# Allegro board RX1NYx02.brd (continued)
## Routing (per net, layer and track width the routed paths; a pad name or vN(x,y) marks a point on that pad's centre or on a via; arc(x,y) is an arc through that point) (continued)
GND_BD2: length 1820
  TOP w0.102: v1(184.07,-56.57) 184.08,-56.58 U27.3
  TOP w0.254: C77.1 195.92,-36.63 v1(195.69,-36.4) ; C78.1 195.92,-39.8 v1(195.69,-39.57) ; C85.2 v1(186.39,-62.01) ; C79.1 195.92,-28.63 v1(195.69,-28.4) ; C83.1 195.92,-33.45 v1(195.69,-33.22) ; U25.9 v1(187.09,-67.25) ; C76.1 v1(187.42,-31.32) ; C75.2 v1(169.39,-48.46) ; C167.2 v1(186.69,-58.17) ; v1(187.45,-37.67) 187.46,-37.67 C82.1
  TOP w0.381: P_OCP2.A38 v1(274.7,-33.22) ; P_OCP2.A28 v1(274.7,-42.63) ; U17.3 187.17,-33.75 186.78,-34.13 v1(186.78,-34.87) ; P_OCP2.A25 v1(274.7,-44.43) ; v1(274.7,-15.11) v1(276.14,-15.11) ; v1(276.14,-49.83) 276.11,-49.86 v1(274.7,-49.86) ; v1(276.14,-16.91) v1(274.7,-16.91) ; U23.3 v1(190.98,-35.14) ; U22.3 187.49,-40.72 187.87,-41.1 v1(188.44,-41.1) ; v1(276.14,-25.91) v1(274.7,-25.91) ; v1(276.14,-51.63) v1(274.7,-51.63) ; v1(276.14,-24.11) v1(274.7,-24.11) ; v1(276.14,-18.71) v1(274.7,-18.71) ; U18.3 v1(190.98,-41.49) ; P_OCP2.A29 v1(274.7,-38.62) ; v1(276.14,-11.51) v1(274.7,-11.51) ; U19.3 v1(190.98,-38.32) ; v1(274.7,-63.82) v1(276.14,-63.82) ; P_OCP2.A32 v1(274.7,-36.82) ; v1(276.14,-65.62) v1(274.7,-65.62) ; v1(276.14,-22.31) v1(274.7,-22.31) ; P_OCP2.A35 v1(274.7,-35.02) ; v1(276.14,-20.51) v1(274.7,-20.51) ; P_OCP2.A19 v1(274.7,-48.03) ; U20.1 v1(179.16,-48.46) ; U21.3 v1(190.98,-30.32) ; v1(276.14,-13.31) v1(274.7,-13.31) ; P_OCP2.A41 v1(274.7,-31.42) ; P_OCP2.A22 v1(274.7,-46.23)
  TOP w0.508: C165.1 179.75,-51.08 v1(179.04,-50.37) ; DS_BD2_PWR.2 v1(172.43,-65.48) ; C156.1 v1(181.5,-63.58) ; SW3.2 v1(186.53,-36.27) ; C158.1 v1(181.5,-68.15) ; Q3.2 v1(171.48,-50.18)
  GND w0.254: 249.52,-73.16 P_BD2_CLK2_P.2 ; P_BD2_CLK2_P.2 250.65,-73.16 ; P_BD2_CLK2_P.2 249.52,-74.29 ; P_BD2_CLK2_P.2 250.65,-74.29 ; 177.59,-17.81 P_OCP_CPU_13_P.4 ; P_OCP_CPU_13_P.4 178.72,-17.81 ; P_OCP_CPU_13_P.4 178.72,-18.94 ; P_OCP_CPU_13_P.4 177.59,-18.94 ; 234.74,-34.67 P_CPU_OCP_13_N.4 ; P_CPU_OCP_13_N.4 235.87,-34.67 ; P_CPU_OCP_13_N.4 234.74,-33.54 ; P_CPU_OCP_13_N.4 235.87,-33.54 ; P_OCP_CPU_10_P.3 201.58,-18.94 ; P_OCP_CPU_10_P.3 200.45,-18.94 ; P_OCP_CPU_10_P.3 200.45,-17.81 ; P_OCP_CPU_10_P.3 201.58,-17.81 ; P_CPU_OCP_8_N.2 263.03,-53.81 ; P_CPU_OCP_8_N.2 261.9,-54.94 ; P_CPU_OCP_8_N.2 263.03,-54.94 ; P_CPU_OCP_8_N.2 261.9,-53.81 ; P_CPU_OCP_12_P.2 247.3,-23.05 ; P_CPU_OCP_12_P.2 246.17,-23.05 ; P_CPU_OCP_12_P.2 246.17,-21.92 ; P_CPU_OCP_12_P.2 247.3,-21.92 ; 193.32,-61.91 P_BD2_CMTS_N.5 ; P_BD2_CMTS_N.5 194.45,-61.91 ; P_BD2_CMTS_N.5 194.45,-60.78 ; P_BD2_CMTS_N.5 193.32,-60.78 ; 200.45,-22.29 P_OCP_CPU_10_P.2 ; P_OCP_CPU_10_P.2 201.58,-22.29 ; P_OCP_CPU_10_P.2 200.45,-21.16 ; P_OCP_CPU_10_P.2 201.58,-21.16 ; P_CPU_OCP_15_P.2 250.65,-12.57 ; P_CPU_OCP_15_P.2 249.52,-12.57 ; P_CPU_OCP_15_P.2 249.52,-11.44 ; P_CPU_OCP_15_P.2 250.65,-11.44 ; P_CPU_OCP_10_N.2 240.17,-54.18 ; P_CPU_OCP_10_N.2 239.04,-53.05 ; P_CPU_OCP_10_N.2 239.04,-54.18 ; P_CPU_OCP_10_N.2 240.17,-53.05 ; 235.69,-11.81 P_CPU_OCP_14_P.5 ; P_CPU_OCP_14_P.5 235.69,-10.68 ; P_CPU_OCP_14_P.5 236.82,-10.68 ; P_CPU_OCP_14_P.5 236.82,-11.81 ; P_BD2_TRIG_IN_N.2 181.75,-69.81 ; P_BD2_TRIG_IN_N.2 180.62,-69.81 ; P_BD2_TRIG_IN_N.2 180.62,-70.94 ; P_BD2_TRIG_IN_N.2 181.75,-70.94 ; 239.04,-56.4 P_CPU_OCP_10_N.3 ; P_CPU_OCP_10_N.3 240.17,-56.4 ; P_CPU_OCP_10_N.3 239.04,-57.53 ; P_CPU_OCP_10_N.3 240.17,-57.53 ; 189.02,-69.81 P_BD2_CMTS_P.5 ; P_BD2_CMTS_P.5 189.02,-70.94 ; P_BD2_CMTS_P.5 190.15,-70.94 ; P_BD2_CMTS_P.5 190.15,-69.81 ; P_OCP_CPU_13_N.5 191.1,-23.24 ; P_OCP_CPU_13_N.5 191.1,-22.11 ; P_OCP_CPU_13_N.5 189.97,-23.24 ; P_OCP_CPU_13_N.5 189.97,-22.11 ; 234.74,-18.94 P_CPU_OCP_13_P.3 ; P_CPU_OCP_13_P.3 235.87,-18.94 ; P_CPU_OCP_13_P.3 234.74,-17.81 ; P_CPU_OCP_13_P.3 235.87,-17.81 ; P_OCP_CPU_9_N.2 217.31,-53.05 ; P_OCP_CPU_9_N.2 217.31,-54.18 ; P_OCP_CPU_9_N.2 216.18,-53.05 ; P_OCP_CPU_9_N.2 216.18,-54.18 ; P_BD2_CMTS_P.2 194.45,-69.81 ; P_BD2_CMTS_P.2 194.45,-70.94 ; P_BD2_CMTS_P.2 193.32,-70.94 ; P_BD2_CMTS_P.2 193.32,-69.81 ; P_BD2_CLK2_N.2 259.68,-68.86 ; P_BD2_CLK2_N.2 258.55,-69.99 ; P_BD2_CLK2_N.2 259.68,-69.99 ; P_BD2_CLK2_N.2 258.55,-68.86 ; P_OCP_CPU_13_P.5 182.07,-17.81 ; P_OCP_CPU_13_P.5 180.94,-17.81 ; P_OCP_CPU_13_P.5 180.94,-18.94 ; P_OCP_CPU_13_P.5 182.07,-18.94 ; P_CPU_OCP_10_P.5 240.17,-45.15 ; P_CPU_OCP_10_P.5 239.04,-44.02 ; P_CPU_OCP_10_P.5 240.17,-44.02 ; P_CPU_OCP_10_P.5 239.04,-45.15 ; 211.88,-45.15 P_OCP_CPU_9_P.2 ; P_OCP_CPU_9_P.2 211.88,-44.02 ; P_OCP_CPU_9_P.2 213.01,-45.15 ; P_OCP_CPU_9_P.2 213.01,-44.02 ; P_OCP_CPU_12_P.3 224.44,-18.94 ; P_OCP_CPU_12_P.3 224.44,-17.81 ; P_OCP_CPU_12_P.3 223.31,-18.94 ; P_OCP_CPU_12_P.3 223.31,-17.81 ; 188.59,-45.39 P8.2 ; P8.2 190.06,-45.39 ; P8.2 188.59,-43.92 ; P8.2 190.06,-43.92 ; P_BD2_CLK1_P.4 201.58,-68.86 ; P_BD2_CLK1_P.4 200.45,-69.99 ; P_BD2_CLK1_P.4 200.45,-68.86 ; P_BD2_CLK1_P.4 201.58,-69.99 ; 227.61,-54.18 P_OCP_CPU_8_N.2 ; P_OCP_CPU_8_N.2 228.74,-54.18 ; P_OCP_CPU_8_N.2 227.61,-53.05 ; P_OCP_CPU_8_N.2 228.74,-53.05 ; P_CPU_OCP_9_N.2 251.6,-54.94 ; P_CPU_OCP_9_N.2 250.47,-53.81 ; P_CPU_OCP_9_N.2 250.47,-54.94 ; P_CPU_OCP_9_N.2 251.6,-53.81 ; P_BD2_CLK0_P.5 227.79,-69.99 ; P_BD2_CLK0_P.5 226.66,-69.99 ; P_BD2_CLK0_P.5 226.66,-68.86 ; P_BD2_CLK0_P.5 227.79,-68.86 ; 223.31,-57.53 P_OCP_CPU_8_N.4 ; P_OCP_CPU_8_N.4 224.44,-57.53 ; P_OCP_CPU_8_N.4 224.44,-56.4 ; P_OCP_CPU_8_N.4 223.31,-56.4 ; 250.47,-18.57 P_CPU_OCP_12_P.4 ; P_CPU_OCP_12_P.4 251.6,-18.57 ; P_CPU_OCP_12_P.4 251.6,-19.7 ; P_CPU_OCP_12_P.4 250.47,-19.7 ; 239.04,-73.16 P_BD2_CLK0_N.4 ; P_BD2_CLK0_N.4 240.17,-74.29 ; P_BD2_CLK0_N.4 239.04,-74.29 ; P_BD2_CLK0_N.4 240.17,-73.16 ; P_BD2_CMTS_P.4 190.15,-73.16 ; P_BD2_CMTS_P.4 189.02,-74.29 ; P_BD2_CMTS_P.4 189.02,-73.16 ; P_BD2_CMTS_P.4 190.15,-74.29 ; P_CPU_OCP_15_N.5 259.68,-12.57 ; P_CPU_OCP_15_N.5 259.68,-11.44 ; P_CPU_OCP_15_N.5 258.55,-11.44 ; P_CPU_OCP_15_N.5 258.55,-12.57 ; 261.9,-57.16 P_CPU_OCP_8_N.3 ; P_CPU_OCP_8_N.3 263.03,-58.29 ; P_CPU_OCP_8_N.3 261.9,-58.29 ; P_CPU_OCP_8_N.3 263.03,-57.16 ; BD2_P_OCP_CPU_0_P.3 201.58,-41.8 ; BD2_P_OCP_CPU_0_P.3 201.58,-40.67 ; BD2_P_OCP_CPU_0_P.3 200.45,-41.8 ; BD2_P_OCP_CPU_0_P.3 200.45,-40.67 ; P_OCP_CPU_11_N.2 217.31,-30.19 ; P_OCP_CPU_11_N.2 216.18,-30.19 ; P_OCP_CPU_11_N.2 217.31,-31.32 ; P_OCP_CPU_11_N.2 216.18,-31.32 ; P_OCP_CPU_12_P.5 228.74,-22.29 ; P_OCP_CPU_12_P.5 227.61,-21.16 ; P_OCP_CPU_12_P.5 227.61,-22.29 ; P_OCP_CPU_12_P.5 228.74,-21.16 ; P_BD2_TRIG_IN_N.3 181.75,-73.16 ; P_BD2_TRIG_IN_N.3 181.75,-74.29 ; P_BD2_TRIG_IN_N.3 180.62,-74.29 ; P_BD2_TRIG_IN_N.3 180.62,-73.16 ; P_OCP_CPU_8_P.5 228.74,-44.02 ; P_OCP_CPU_8_P.5 227.61,-45.15 ; P_OCP_CPU_8_P.5 227.61,-44.02 ; P_OCP_CPU_8_P.5 228.74,-45.15 ; P_OCP_CPU_9_N.3 217.31,-56.4 ; P_OCP_CPU_9_N.3 216.18,-57.53 ; P_OCP_CPU_9_N.3 216.18,-56.4 ; P_OCP_CPU_9_N.3 217.31,-57.53 ; 193.32,-6.38 P_OCP_CPU_14_P.3 ; P_OCP_CPU_14_P.3 194.45,-7.51 ; P_OCP_CPU_14_P.3 193.32,-7.51 ; P_OCP_CPU_14_P.3 194.45,-6.38 ; P_CPU_OCP_12_N.2 251.6,-32.08 ; P_CPU_OCP_12_N.2 250.47,-30.95 ; P_CPU_OCP_12_N.2 251.6,-30.95 ; P_CPU_OCP_12_N.2 250.47,-32.08 ; 250.47,-41.43 P_CPU_OCP_9_P.4 ; P_CPU_OCP_9_P.4 250.47,-42.56 ; P_CPU_OCP_9_P.4 251.6,-42.56 ; P_CPU_OCP_9_P.4 251.6,-41.43 ; P_CPU_OCP_11_N.2 263.03,-30.95 ; P_CPU_OCP_11_N.2 261.9,-32.08 ; P_CPU_OCP_11_N.2 261.9,-30.95 ; P_CPU_OCP_11_N.2 263.03,-32.08 ; 257.6,-35.43 P_CPU_OCP_11_N.4 ; P_CPU_OCP_11_N.4 258.73,-35.43 ; P_CPU_OCP_11_N.4 258.73,-34.3 ; P_CPU_OCP_11_N.4 257.6,-34.3 ; 211.88,-34.67 P_OCP_CPU_11_N.4 ; P_OCP_CPU_11_N.4 211.88,-33.54 ; P_OCP_CPU_11_N.4 213.01,-33.54 ; P_OCP_CPU_11_N.4 213.01,-34.67 ; 223.31,-30.19 P_OCP_CPU_12_N.5 ; P_OCP_CPU_12_N.5 223.31,-31.32 ; P_OCP_CPU_12_N.5 224.44,-31.32 ; P_OCP_CPU_12_N.5 224.44,-30.19 ; P_OCP_CPU_8_P.2 224.44,-44.02 ; P_OCP_CPU_8_P.2 223.31,-44.02 ; P_OCP_CPU_8_P.2 223.31,-45.15 ; P_OCP_CPU_8_P.2 224.44,-45.15 ; 200.45,-56.4 BD2_P_OCP_CPU_0_N.4 ; BD2_P_OCP_CPU_0_N.4 200.45,-57.53 ; BD2_P_OCP_CPU_0_N.4 201.58,-57.53 ; BD2_P_OCP_CPU_0_N.4 201.58,-56.4 ; 223.31,-6.38 P_CPU_OCP_14_N.4 ; P_CPU_OCP_14_N.4 223.31,-7.51 ; P_CPU_OCP_14_N.4 224.44,-6.38 ; P_CPU_OCP_14_N.4 224.44,-7.51 ; P_BD2_TRIG_IN_P.3 177.45,-58.56 ; P_BD2_TRIG_IN_P.3 176.32,-58.56 ; P_BD2_TRIG_IN_P.3 177.45,-57.43 ; P_BD2_TRIG_IN_P.3 176.32,-57.43 ; P_CPU_OCP_10_P.2 235.87,-44.02 ; P_CPU_OCP_10_P.2 234.74,-45.15 ; P_CPU_OCP_10_P.2 234.74,-44.02 ; P_CPU_OCP_10_P.2 235.87,-45.15 ; P_CPU_OCP_15_P.3 247.3,-11.44 ; P_CPU_OCP_15_P.3 246.17,-12.57 ; P_CPU_OCP_15_P.3 246.17,-11.44 ; P_CPU_OCP_15_P.3 247.3,-12.57 ; P_CPU_OCP_13_N.2 240.17,-31.32 ; P_CPU_OCP_13_N.2 240.17,-30.19 ; P_CPU_OCP_13_N.2 239.04,-30.19 ; P_CPU_OCP_13_N.2 239.04,-31.32 ; 246.17,-8.27 P_CPU_OCP_15_P.4 ; P_CPU_OCP_15_P.4 246.17,-7.14 ; P_CPU_OCP_15_P.4 247.3,-8.27 ; P_CPU_OCP_15_P.4 247.3,-7.14 ; P_CPU_OCP_8_P.2 258.73,-45.91 ; P_CPU_OCP_8_P.2 257.6,-44.78 ; P_CPU_OCP_8_P.2 257.6,-45.91 ; P_CPU_OCP_8_P.2 258.73,-44.78 ; P_OCP_CPU_8_N.3 228.74,-57.53 ; P_OCP_CPU_8_N.3 228.74,-56.4 ; P_OCP_CPU_8_N.3 227.61,-57.53 ; P_OCP_CPU_8_N.3 227.61,-56.4 ; P_OCP_CPU_10_P.5 205.88,-21.16 ; P_OCP_CPU_10_P.5 204.75,-22.29 ; P_OCP_CPU_10_P.5 204.75,-21.16 ; P_OCP_CPU_10_P.5 205.88,-22.29 ; 257.6,-41.43 P_CPU_OCP_8_P.3 ; P_CPU_OCP_8_P.3 258.73,-42.56 ; P_CPU_OCP_8_P.3 257.6,-42.56 ; P_CPU_OCP_8_P.3 258.73,-41.43 ; 204.75,-40.67 BD2_P_OCP_CPU_0_P.4 ; BD2_P_OCP_CPU_0_P.4 204.75,-41.8 ; BD2_P_OCP_CPU_0_P.4 205.88,-40.67 ; BD2_P_OCP_CPU_0_P.4 205.88,-41.8 ; P_BD2_CLK1_P.5 204.93,-69.99 ; P_BD2_CLK1_P.5 204.93,-68.86 ; P_BD2_CLK1_P.5 203.8,-68.86 ; P_BD2_CLK1_P.5 203.8,-69.99 ; P_BD2_CLK0_P.4 224.44,-69.99 ; P_BD2_CLK0_P.4 223.31,-68.86 ; P_BD2_CLK0_P.4 224.44,-68.86 ; P_BD2_CLK0_P.4 223.31,-69.99 ; 180.94,-6.38 P_OCP_CPU_14_N.5 ; P_OCP_CPU_14_N.5 180.94,-7.51 ; P_OCP_CPU_14_N.5 182.07,-6.38 ; P_OCP_CPU_14_N.5 182.07,-7.51 ; 227.61,-40.67 P_OCP_CPU_8_P.4 ; P_OCP_CPU_8_P.4 228.74,-40.67 ; P_OCP_CPU_8_P.4 227.61,-41.8 ; P_OCP_CPU_8_P.4 228.74,-41.8 ; 216.18,-45.15 P_OCP_CPU_9_P.5 ; P_OCP_CPU_9_P.5 217.31,-44.02 ; P_OCP_CPU_9_P.5 217.31,-45.15 ; P_OCP_CPU_9_P.5 216.18,-44.02 ; P_CPU_OCP_8_P.4 263.03,-41.43 ; P_CPU_OCP_8_P.4 263.03,-42.56 ; P_CPU_OCP_8_P.4 261.9,-42.56 ; P_CPU_OCP_8_P.4 261.9,-41.43 ; P9.2 185.61,-45.39 ; P9.2 185.61,-43.92 ; P9.2 184.15,-43.92 ; P9.2 184.15,-45.39 ; P_OCP_CPU_10_N.2 205.88,-31.32 ; P_OCP_CPU_10_N.2 204.75,-31.32 ; P_OCP_CPU_10_N.2 204.75,-30.19 ; P_OCP_CPU_10_N.2 205.88,-30.19 ; 246.17,-45.91 P_CPU_OCP_9_P.2 ; P_CPU_OCP_9_P.2 247.3,-44.78 ; P_CPU_OCP_9_P.2 246.17,-44.78 ; P_CPU_OCP_9_P.2 247.3,-45.91 ; P_OCP_CPU_14_N.4 178.72,-6.38 ; P_OCP_CPU_14_N.4 178.72,-7.51 ; P_OCP_CPU_14_N.4 177.59,-6.38 ; P_OCP_CPU_14_N.4 177.59,-7.51 ; P_OCP_CPU_13_N.3 194.45,-17.81 ; P_OCP_CPU_13_N.3 193.32,-18.94 ; P_OCP_CPU_13_N.3 193.32,-17.81 ; P_OCP_CPU_13_N.3 194.45,-18.94 ; P_OCP_CPU_15_P.3 217.31,-7.51 ; P_OCP_CPU_15_P.3 216.18,-6.38 ; P_OCP_CPU_15_P.3 217.31,-6.38 ; P_OCP_CPU_15_P.3 216.18,-7.51 ; P_OCP_CPU_15_P.4 217.31,-11.81 ; P_OCP_CPU_15_P.4 216.18,-10.68 ; P_OCP_CPU_15_P.4 216.18,-11.81 ; P_OCP_CPU_15_P.4 217.31,-10.68 ; 211.88,-21.16 P_OCP_CPU_11_P.2 ; P_OCP_CPU_11_P.2 213.01,-22.29 ; P_OCP_CPU_11_P.2 211.88,-22.29 ; P_OCP_CPU_11_P.2 213.01,-21.16 ; 216.18,-33.54 P_OCP_CPU_11_N.3 ; P_OCP_CPU_11_N.3 217.31,-34.67 ; P_OCP_CPU_11_N.3 217.31,-33.54 ; P_OCP_CPU_11_N.3 216.18,-34.67 ; 250.47,-44.78 P_CPU_OCP_9_P.5 ; P_CPU_OCP_9_P.5 250.47,-45.91 ; P_CPU_OCP_9_P.5 251.6,-44.78 ; P_CPU_OCP_9_P.5 251.6,-45.91 ; P_CPU_OCP_14_N.5 227.79,-7.51 ; P_CPU_OCP_14_N.5 226.66,-6.38 ; P_CPU_OCP_14_N.5 227.79,-6.38 ; P_CPU_OCP_14_N.5 226.66,-7.51 ; P_CPU_OCP_13_P.2 235.87,-22.29 ; P_CPU_OCP_13_P.2 235.87,-21.16 ; P_CPU_OCP_13_P.2 234.74,-22.29 ; P_CPU_OCP_13_P.2 234.74,-21.16 ; P_BD2_CLK1_N.2 213.96,-68.86 ; P_BD2_CLK1_N.2 212.83,-69.99 ; P_BD2_CLK1_N.2 213.96,-69.99 ; P_BD2_CLK1_N.2 212.83,-68.86 ; 193.32,-10.68 P_OCP_CPU_14_P.4 ; P_OCP_CPU_14_P.4 194.45,-11.81 ; P_OCP_CPU_14_P.4 193.32,-11.81 ; P_OCP_CPU_14_P.4 194.45,-10.68 ; P_OCP_CPU_12_N.3 228.74,-33.54 ; P_OCP_CPU_12_N.3 227.61,-34.67 ; P_OCP_CPU_12_N.3 227.61,-33.54 ; P_OCP_CPU_12_N.3 228.74,-34.67 ; P_OCP_CPU_10_P.4 205.88,-17.81 ; P_OCP_CPU_10_P.4 205.88,-18.94 ; P_OCP_CPU_10_P.4 204.75,-17.81 ; P_OCP_CPU_10_P.4 204.75,-18.94 ; P_CPU_OCP_12_N.3 251.6,-35.43 ; P_CPU_OCP_12_N.3 250.47,-34.3 ; P_CPU_OCP_12_N.3 250.47,-35.43 ; P_CPU_OCP_12_N.3 251.6,-34.3 ; P_BD2_CLK1_N.5 213.96,-73.16 ; P_BD2_CLK1_N.5 213.96,-74.29 ; P_BD2_CLK1_N.5 212.83,-74.29 ; P_BD2_CLK1_N.5 212.83,-73.16 ; 204.75,-45.15 BD2_P_OCP_CPU_0_P.5 ; BD2_P_OCP_CPU_0_P.5 205.88,-45.15 ; BD2_P_OCP_CPU_0_P.5 204.75,-44.02 ; BD2_P_OCP_CPU_0_P.5 205.88,-44.02 ; P_OCP_CPU_10_N.4 201.58,-34.67 ; P_OCP_CPU_10_N.4 200.45,-34.67 ; P_OCP_CPU_10_N.4 200.45,-33.54 ; P_OCP_CPU_10_N.4 201.58,-33.54 ; 216.18,-73.16 P_BD2_CLK1_N.4 ; P_BD2_CLK1_N.4 216.18,-74.29 ; P_BD2_CLK1_N.4 217.31,-73.16 ; P_BD2_CLK1_N.4 217.31,-74.29 ; P_OCP_CPU_10_N.5 201.58,-31.32 ; P_OCP_CPU_10_N.5 200.45,-30.19 ; P_OCP_CPU_10_N.5 201.58,-30.19 ; P_OCP_CPU_10_N.5 200.45,-31.32 ; 250.47,-57.16 P_CPU_OCP_9_N.3 ; P_CPU_OCP_9_N.3 250.47,-58.29 ; P_CPU_OCP_9_N.3 251.6,-58.29 ; P_CPU_OCP_9_N.3 251.6,-57.16 ; P_BD2_CLK2_N.4 263.03,-74.29 ; P_BD2_CLK2_N.4 261.9,-73.16 ; P_BD2_CLK2_N.4 263.03,-73.16 ; P_BD2_CLK2_N.4 261.9,-74.29 ; P_OCP_CPU_14_P.2 191.1,-6.38 ; P_OCP_CPU_14_P.2 191.1,-7.51 ; P_OCP_CPU_14_P.2 189.97,-7.51 ; P_OCP_CPU_14_P.2 189.97,-6.38 ; 203.8,-73.16 P_BD2_CLK1_P.2 ; P_BD2_CLK1_P.2 204.93,-73.16 ; P_BD2_CLK1_P.2 203.8,-74.29 ; P_BD2_CLK1_P.2 204.93,-74.29 ; P_CPU_OCP_11_N.5 258.73,-32.08 ; P_CPU_OCP_11_N.5 257.6,-30.95 ; P_CPU_OCP_11_N.5 257.6,-32.08 ; P_CPU_OCP_11_N.5 258.73,-30.95 ; P_CPU_OCP_9_P.3 247.3,-42.56 ; P_CPU_OCP_9_P.3 246.17,-41.43 ; P_CPU_OCP_9_P.3 246.17,-42.56 ; P_CPU_OCP_9_P.3 247.3,-41.43 ; P_CPU_OCP_13_N.3 240.17,-34.67 ; P_CPU_OCP_13_N.3 240.17,-33.54 ; P_CPU_OCP_13_N.3 239.04,-33.54 ; P_CPU_OCP_13_N.3 239.04,-34.67 ; 204.75,-54.18 BD2_P_OCP_CPU_0_N.2 ; BD2_P_OCP_CPU_0_N.2 205.88,-53.05 ; BD2_P_OCP_CPU_0_N.2 204.75,-53.05 ; BD2_P_OCP_CPU_0_N.2 205.88,-54.18 ; 211.88,-54.18 P_OCP_CPU_9_N.5 ; P_OCP_CPU_9_N.5 213.01,-54.18 ; P_OCP_CPU_9_N.5 211.88,-53.05 ; P_OCP_CPU_9_N.5 213.01,-53.05 ; 223.31,-21.16 P_OCP_CPU_12_P.2 ; P_OCP_CPU_12_P.2 224.44,-21.16 ; P_OCP_CPU_12_P.2 223.31,-22.29 ; P_OCP_CPU_12_P.2 224.44,-22.29 ; P7.2 194.5,-43.92 ; P7.2 193.04,-45.39 ; P7.2 194.5,-45.39 ; P7.2 193.04,-43.92 ; 193.32,-23.24 P_OCP_CPU_13_N.4 ; P_OCP_CPU_13_N.4 194.45,-22.11 ; P_OCP_CPU_13_N.4 194.45,-23.24 ; P_OCP_CPU_13_N.4 193.32,-22.11 ; P_BD2_CMTS_P.3 194.45,-74.29 ; P_BD2_CMTS_P.3 193.32,-73.16 ; P_BD2_CMTS_P.3 194.45,-73.16 ; P_BD2_CMTS_P.3 193.32,-74.29 ; 261.9,-18.57 P_CPU_OCP_11_P.4 ; P_CPU_OCP_11_P.4 261.9,-19.7 ; P_CPU_OCP_11_P.4 263.03,-18.57 ; P_CPU_OCP_11_P.4 263.03,-19.7 ; P_OCP_CPU_12_P.4 228.74,-18.94 ; P_OCP_CPU_12_P.4 227.61,-17.81 ; P_OCP_CPU_12_P.4 227.61,-18.94 ; P_OCP_CPU_12_P.4 228.74,-17.81 ; 261.9,-21.92 P_CPU_OCP_11_P.5 ; P_CPU_OCP_11_P.5 263.03,-21.92 ; P_CPU_OCP_11_P.5 263.03,-23.05 ; P_CPU_OCP_11_P.5 261.9,-23.05 ; 180.62,-60.78 P_BD2_TRIG_IN_P.5 ; P_BD2_TRIG_IN_P.5 181.75,-61.91 ; P_BD2_TRIG_IN_P.5 181.75,-60.78 ; P_BD2_TRIG_IN_P.5 180.62,-61.91 ; 234.74,-40.67 P_CPU_OCP_10_P.3 ; P_CPU_OCP_10_P.3 235.87,-40.67 ; P_CPU_OCP_10_P.3 235.87,-41.8 ; P_CPU_OCP_10_P.3 234.74,-41.8 ; P_CPU_OCP_15_N.4 263.03,-12.57 ; P_CPU_OCP_15_N.4 261.9,-11.44 ; P_CPU_OCP_15_N.4 261.9,-12.57 ; P_CPU_OCP_15_N.4 263.03,-11.44 ; P_OCP_CPU_9_P.4 217.31,-41.8 ; P_OCP_CPU_9_P.4 216.18,-40.67 ; P_OCP_CPU_9_P.4 216.18,-41.8 ; P_OCP_CPU_9_P.4 217.31,-40.67 ; 250.47,-23.05 P_CPU_OCP_12_P.5 ; P_CPU_OCP_12_P.5 251.6,-23.05 ; P_CPU_OCP_12_P.5 250.47,-21.92 ; P_CPU_OCP_12_P.5 251.6,-21.92 ; P_BD2_CMTS_N.3 190.15,-57.43 ; P_BD2_CMTS_N.3 189.02,-58.56 ; P_BD2_CMTS_N.3 189.02,-57.43 ; P_BD2_CMTS_N.3 190.15,-58.56 ; P_BD2_CLK1_P.3 201.58,-73.16 ; P_BD2_CLK1_P.3 201.58,-74.29 ; P_BD2_CLK1_P.3 200.45,-73.16 ; P_BD2_CLK1_P.3 200.45,-74.29 ; P_CPU_OCP_9_N.4 247.3,-57.16 ; P_CPU_OCP_9_N.4 246.17,-58.29 ; P_CPU_OCP_9_N.4 247.3,-58.29 ; P_CPU_OCP_9_N.4 246.17,-57.16 ; P_OCP_CPU_12_N.4 224.44,-33.54 ; P_OCP_CPU_12_N.4 224.44,-34.67 ; P_OCP_CPU_12_N.4 223.31,-33.54 ; P_OCP_CPU_12_N.4 223.31,-34.67 ; 261.9,-34.3 P_CPU_OCP_11_N.3 ; P_CPU_OCP_11_N.3 261.9,-35.43 ; P_CPU_OCP_11_N.3 263.03,-34.3 ; P_CPU_OCP_11_N.3 263.03,-35.43 ; 216.18,-21.16 P_OCP_CPU_11_P.5 ; P_OCP_CPU_11_P.5 217.31,-21.16 ; P_OCP_CPU_11_P.5 217.31,-22.29 ; P_OCP_CPU_11_P.5 216.18,-22.29 ; P_BD2_CLK2_P.5 250.65,-68.86 ; P_BD2_CLK2_P.5 250.65,-69.99 ; P_BD2_CLK2_P.5 249.52,-69.99 ; P_BD2_CLK2_P.5 249.52,-68.86 ; P_BD2_CLK2_N.3 263.03,-68.86 ; P_BD2_CLK2_N.3 261.9,-69.99 ; P_BD2_CLK2_N.3 261.9,-68.86 ; P_BD2_CLK2_N.3 263.03,-69.99 ; P_OCP_CPU_14_N.3 178.72,-10.68 ; P_OCP_CPU_14_N.3 177.59,-10.68 ; P_OCP_CPU_14_N.3 177.59,-11.81 ; P_OCP_CPU_14_N.3 178.72,-11.81 ; P_OCP_CPU_9_N.4 213.01,-56.4 ; P_OCP_CPU_9_N.4 211.88,-57.53 ; P_OCP_CPU_9_N.4 211.88,-56.4 ; P_OCP_CPU_9_N.4 213.01,-57.53 ; 212.83,-11.81 P_OCP_CPU_15_P.5 ; P_OCP_CPU_15_P.5 212.83,-10.68 ; P_OCP_CPU_15_P.5 213.96,-11.81 ; P_OCP_CPU_15_P.5 213.96,-10.68 ; 249.52,-8.27 P_CPU_OCP_15_P.5 ; P_CPU_OCP_15_P.5 250.65,-7.14 ; P_CPU_OCP_15_P.5 249.52,-7.14 ; P_CPU_OCP_15_P.5 250.65,-8.27 ; 257.6,-23.05 P_CPU_OCP_11_P.2 ; P_CPU_OCP_11_P.2 257.6,-21.92 ; P_CPU_OCP_11_P.2 258.73,-21.92 ; P_CPU_OCP_11_P.2 258.73,-23.05 ; P_CPU_OCP_14_P.4 240.17,-11.81 ; P_CPU_OCP_14_P.4 239.04,-11.81 ; P_CPU_OCP_14_P.4 240.17,-10.68 ; P_CPU_OCP_14_P.4 239.04,-10.68 ; 239.04,-40.67 P_CPU_OCP_10_P.4 ; P_CPU_OCP_10_P.4 240.17,-41.8 ; P_CPU_OCP_10_P.4 239.04,-41.8 ; P_CPU_OCP_10_P.4 240.17,-40.67 ; 211.88,-40.67 P_OCP_CPU_9_P.3 ; P_OCP_CPU_9_P.3 213.01,-41.8 ; P_OCP_CPU_9_P.3 213.01,-40.67 ; P_OCP_CPU_9_P.3 211.88,-41.8 ; 176.32,-61.91 P_BD2_TRIG_IN_P.2 ; P_BD2_TRIG_IN_P.2 177.45,-61.91 ; P_BD2_TRIG_IN_P.2 177.45,-60.78 ; P_BD2_TRIG_IN_P.2 176.32,-60.78 ; 246.17,-18.57 P_CPU_OCP_12_P.3 ; P_CPU_OCP_12_P.3 247.3,-18.57 ; P_CPU_OCP_12_P.3 246.17,-19.7 ; P_CPU_OCP_12_P.3 247.3,-19.7 ; P_CPU_OCP_12_N.4 247.3,-35.43 ; P_CPU_OCP_12_N.4 247.3,-34.3 ; P_CPU_OCP_12_N.4 246.17,-35.43 ; P_CPU_OCP_12_N.4 246.17,-34.3 ; 211.88,-31.32 P_OCP_CPU_11_N.5 ; P_OCP_CPU_11_N.5 213.01,-31.32 ; P_OCP_CPU_11_N.5 213.01,-30.19 ; P_OCP_CPU_11_N.5 211.88,-30.19 ; 227.61,-31.32 P_OCP_CPU_12_N.2 ; P_OCP_CPU_12_N.2 228.74,-31.32 ; P_OCP_CPU_12_N.2 228.74,-30.19 ; P_OCP_CPU_12_N.2 227.61,-30.19 ; 203.8,-6.38 P_OCP_CPU_15_N.5 ; P_OCP_CPU_15_N.5 204.93,-6.38 ; P_OCP_CPU_15_N.5 203.8,-7.51 ; P_OCP_CPU_15_N.5 204.93,-7.51 ; P_OCP_CPU_10_N.3 205.88,-33.54 ; P_OCP_CPU_10_N.3 204.75,-33.54 ; P_OCP_CPU_10_N.3 205.88,-34.67 ; P_OCP_CPU_10_N.3 204.75,-34.67 ; P_BD2_CLK2_P.3 247.3,-73.16 ; P_BD2_CLK2_P.3 246.17,-73.16 ; P_BD2_CLK2_P.3 246.17,-74.29 ; P_BD2_CLK2_P.3 247.3,-74.29 ; 235.69,-7.51 P_CPU_OCP_14_P.2 ; P_CPU_OCP_14_P.2 236.82,-7.51 ; P_CPU_OCP_14_P.2 236.82,-6.38 ; P_CPU_OCP_14_P.2 235.69,-6.38 ; 261.9,-7.14 P_CPU_OCP_15_N.3 ; P_CPU_OCP_15_N.3 263.03,-8.27 ; P_CPU_OCP_15_N.3 261.9,-8.27 ; P_CPU_OCP_15_N.3 263.03,-7.14 ; 226.66,-73.16 P_BD2_CLK0_P.2 ; P_BD2_CLK0_P.2 227.79,-74.29 ; P_BD2_CLK0_P.2 226.66,-74.29 ; P_BD2_CLK0_P.2 227.79,-73.16 ; 212.83,-6.38 P_OCP_CPU_15_P.2 ; P_OCP_CPU_15_P.2 213.96,-7.51 ; P_OCP_CPU_15_P.2 213.96,-6.38 ; P_OCP_CPU_15_P.2 212.83,-7.51 ; 200.45,-7.51 P_OCP_CPU_15_N.4 ; P_OCP_CPU_15_N.4 201.58,-6.38 ; P_OCP_CPU_15_N.4 200.45,-6.38 ; P_OCP_CPU_15_N.4 201.58,-7.51 ; 223.31,-74.29 P_BD2_CLK0_P.3 ; P_BD2_CLK0_P.3 223.31,-73.16 ; P_BD2_CLK0_P.3 224.44,-73.16 ; P_BD2_CLK0_P.3 224.44,-74.29 ; P_CPU_OCP_10_N.5 235.87,-53.05 ; P_CPU_OCP_10_N.5 234.74,-53.05 ; P_CPU_OCP_10_N.5 234.74,-54.18 ; P_CPU_OCP_10_N.5 235.87,-54.18 ; 200.45,-44.02 BD2_P_OCP_CPU_0_P.2 ; BD2_P_OCP_CPU_0_P.2 200.45,-45.15 ; BD2_P_OCP_CPU_0_P.2 201.58,-44.02 ; BD2_P_OCP_CPU_0_P.2 201.58,-45.15 ; 239.04,-17.81 P_CPU_OCP_13_P.4 ; P_CPU_OCP_13_P.4 239.04,-18.94 ; P_CPU_OCP_13_P.4 240.17,-17.81 ; P_CPU_OCP_13_P.4 240.17,-18.94 ; 239.04,-69.99 P_BD2_CLK0_N.3 ; P_BD2_CLK0_N.3 240.17,-69.99 ; P_BD2_CLK0_N.3 240.17,-68.86 ; P_BD2_CLK0_N.3 239.04,-68.86 ; 193.32,-58.56 P_BD2_CMTS_N.4 ; P_BD2_CMTS_N.4 194.45,-57.43 ; P_BD2_CMTS_N.4 193.32,-57.43 ; P_BD2_CMTS_N.4 194.45,-58.56 ; P_BD2_TRIG_IN_N.4 177.45,-74.29 ; P_BD2_TRIG_IN_N.4 177.45,-73.16 ; P_BD2_TRIG_IN_N.4 176.32,-73.16 ; P_BD2_TRIG_IN_N.4 176.32,-74.29 ; 257.6,-54.94 P_CPU_OCP_8_N.5 ; P_CPU_OCP_8_N.5 258.73,-54.94 ; P_CPU_OCP_8_N.5 258.73,-53.81 ; P_CPU_OCP_8_N.5 257.6,-53.81 ; P_BD2_CLK0_N.2 236.82,-69.99 ; P_BD2_CLK0_N.2 235.69,-69.99 ; P_BD2_CLK0_N.2 235.69,-68.86 ; P_BD2_CLK0_N.2 236.82,-68.86 ; 223.31,-40.67 P_OCP_CPU_8_P.3 ; P_OCP_CPU_8_P.3 224.44,-41.8 ; P_OCP_CPU_8_P.3 223.31,-41.8 ; P_OCP_CPU_8_P.3 224.44,-40.67 ; 189.97,-18.94 P_OCP_CPU_13_N.2 ; P_OCP_CPU_13_N.2 191.1,-18.94 ; P_OCP_CPU_13_N.2 189.97,-17.81 ; P_OCP_CPU_13_N.2 191.1,-17.81 ; 189.97,-11.81 P_OCP_CPU_14_P.5 ; P_OCP_CPU_14_P.5 191.1,-10.68 ; P_OCP_CPU_14_P.5 189.97,-10.68 ; P_OCP_CPU_14_P.5 191.1,-11.81 ; 258.55,-8.27 P_CPU_OCP_15_N.2 ; P_CPU_OCP_15_N.2 259.68,-8.27 ; P_CPU_OCP_15_N.2 259.68,-7.14 ; P_CPU_OCP_15_N.2 258.55,-7.14 ; 200.45,-54.18 BD2_P_OCP_CPU_0_N.5 ; BD2_P_OCP_CPU_0_N.5 201.58,-54.18 ; BD2_P_OCP_CPU_0_N.5 201.58,-53.05 ; BD2_P_OCP_CPU_0_N.5 200.45,-53.05 ; 184.02,-51.03 P15.2 ; P15.2 185.49,-52.5 ; P15.2 185.49,-51.03 ; P15.2 184.02,-52.5 ; 216.18,-17.81 P_OCP_CPU_11_P.4 ; P_OCP_CPU_11_P.4 216.18,-18.94 ; P_OCP_CPU_11_P.4 217.31,-18.94 ; P_OCP_CPU_11_P.4 217.31,-17.81 ; 203.8,-11.81 P_OCP_CPU_15_N.2 ; P_OCP_CPU_15_N.2 204.93,-11.81 ; P_OCP_CPU_15_N.2 203.8,-10.68 ; P_OCP_CPU_15_N.2 204.93,-10.68 ; 257.6,-57.16 P_CPU_OCP_8_N.4 ; P_CPU_OCP_8_N.4 257.6,-58.29 ; P_CPU_OCP_8_N.4 258.73,-57.16 ; P_CPU_OCP_8_N.4 258.73,-58.29 ; 246.17,-32.08 P_CPU_OCP_12_N.5 ; P_CPU_OCP_12_N.5 247.3,-30.95 ; P_CPU_OCP_12_N.5 247.3,-32.08 ; P_CPU_OCP_12_N.5 246.17,-30.95 ; P_BD2_CMTS_N.2 190.15,-61.91 ; P_BD2_CMTS_N.2 189.02,-60.78 ; P_BD2_CMTS_N.2 189.02,-61.91 ; P_BD2_CMTS_N.2 190.15,-60.78 ; 223.31,-11.81 P_CPU_OCP_14_N.3 ; P_CPU_OCP_14_N.3 223.31,-10.68 ; P_CPU_OCP_14_N.3 224.44,-10.68 ; P_CPU_OCP_14_N.3 224.44,-11.81 ; P_OCP_CPU_14_N.2 182.07,-11.81 ; P_OCP_CPU_14_N.2 180.94,-11.81 ; P_OCP_CPU_14_N.2 182.07,-10.68 ; P_OCP_CPU_14_N.2 180.94,-10.68 ; P_OCP_CPU_13_P.2 182.07,-22.11 ; P_OCP_CPU_13_P.2 180.94,-22.11 ; P_OCP_CPU_13_P.2 180.94,-23.24 ; P_OCP_CPU_13_P.2 182.07,-23.24 ; 257.6,-18.57 P_CPU_OCP_11_P.3 ; P_CPU_OCP_11_P.3 258.73,-18.57 ; P_CPU_OCP_11_P.3 258.73,-19.7 ; P_CPU_OCP_11_P.3 257.6,-19.7 ; BD2_P_OCP_CPU_0_N.3 205.88,-56.4 ; BD2_P_OCP_CPU_0_N.3 204.75,-56.4 ; BD2_P_OCP_CPU_0_N.3 205.88,-57.53 ; BD2_P_OCP_CPU_0_N.3 204.75,-57.53 ; 246.17,-54.94 P_CPU_OCP_9_N.5 ; P_CPU_OCP_9_N.5 247.3,-53.81 ; P_CPU_OCP_9_N.5 246.17,-53.81 ; P_CPU_OCP_9_N.5 247.3,-54.94 ; 234.74,-31.32 P_CPU_OCP_13_N.5 ; P_CPU_OCP_13_N.5 235.87,-31.32 ; P_CPU_OCP_13_N.5 235.87,-30.19 ; P_CPU_OCP_13_N.5 234.74,-30.19 ; P_BD2_CLK0_N.5 236.82,-73.16 ; P_BD2_CLK0_N.5 235.69,-74.29 ; P_BD2_CLK0_N.5 235.69,-73.16 ; P_BD2_CLK0_N.5 236.82,-74.29 ; 200.45,-11.81 P_OCP_CPU_15_N.3 ; P_OCP_CPU_15_N.3 201.58,-11.81 ; P_OCP_CPU_15_N.3 200.45,-10.68 ; P_OCP_CPU_15_N.3 201.58,-10.68 ; P_CPU_OCP_14_N.2 227.79,-11.81 ; P_CPU_OCP_14_N.2 226.66,-10.68 ; P_CPU_OCP_14_N.2 226.66,-11.81 ; P_CPU_OCP_14_N.2 227.79,-10.68 ; P_BD2_TRIG_IN_P.4 181.75,-58.56 ; P_BD2_TRIG_IN_P.4 180.62,-57.43 ; P_BD2_TRIG_IN_P.4 180.62,-58.56 ; P_BD2_TRIG_IN_P.4 181.75,-57.43 ; 258.55,-74.29 P_BD2_CLK2_N.5 ; P_BD2_CLK2_N.5 259.68,-74.29 ; P_BD2_CLK2_N.5 259.68,-73.16 ; P_BD2_CLK2_N.5 258.55,-73.16 ; 176.32,-69.81 P_BD2_TRIG_IN_N.5 ; P_BD2_TRIG_IN_N.5 177.45,-70.94 ; P_BD2_TRIG_IN_N.5 176.32,-70.94 ; P_BD2_TRIG_IN_N.5 177.45,-69.81 ; P_OCP_CPU_11_P.3 213.01,-17.81 ; P_OCP_CPU_11_P.3 211.88,-17.81 ; P_OCP_CPU_11_P.3 213.01,-18.94 ; P_OCP_CPU_11_P.3 211.88,-18.94 ; 246.17,-69.99 P_BD2_CLK2_P.4 ; P_BD2_CLK2_P.4 247.3,-68.86 ; P_BD2_CLK2_P.4 246.17,-68.86 ; P_BD2_CLK2_P.4 247.3,-69.99 ; 177.59,-22.11 P_OCP_CPU_13_P.3 ; P_OCP_CPU_13_P.3 178.72,-22.11 ; P_OCP_CPU_13_P.3 177.59,-23.24 ; P_OCP_CPU_13_P.3 178.72,-23.24 ; P_BD2_CLK1_N.3 217.31,-69.99 ; P_BD2_CLK1_N.3 216.18,-68.86 ; P_BD2_CLK1_N.3 216.18,-69.99 ; P_BD2_CLK1_N.3 217.31,-68.86 ; P_OCP_CPU_8_N.5 224.44,-53.05 ; P_OCP_CPU_8_N.5 224.44,-54.18 ; P_OCP_CPU_8_N.5 223.31,-54.18 ; P_OCP_CPU_8_N.5 223.31,-53.05 ; P_CPU_OCP_13_P.5 240.17,-21.16 ; P_CPU_OCP_13_P.5 240.17,-22.29 ; P_CPU_OCP_13_P.5 239.04,-21.16 ; P_CPU_OCP_13_P.5 239.04,-22.29 ; 234.74,-57.53 P_CPU_OCP_10_N.4 ; P_CPU_OCP_10_N.4 234.74,-56.4 ; P_CPU_OCP_10_N.4 235.87,-57.53 ; P_CPU_OCP_10_N.4 235.87,-56.4 ; P_CPU_OCP_8_P.5 263.03,-44.78 ; P_CPU_OCP_8_P.5 263.03,-45.91 ; P_CPU_OCP_8_P.5 261.9,-45.91 ; P_CPU_OCP_8_P.5 261.9,-44.78 ; 239.04,-6.38 P_CPU_OCP_14_P.3 ; P_CPU_OCP_14_P.3 239.04,-7.51 ; P_CPU_OCP_14_P.3 240.17,-6.38 ; P_CPU_OCP_14_P.3 240.17,-7.51
  GD2 w0.254: P9.2 185.61,-43.92 ; P9.2 184.15,-45.39 ; P9.2 185.61,-45.39 ; P9.2 184.15,-43.92 ; 193.32,-61.91 P_BD2_CMTS_N.5 ; P_BD2_CMTS_N.5 194.45,-61.91 ; P_BD2_CMTS_N.5 193.32,-60.78 ; P_BD2_CMTS_N.5 194.45,-60.78 ; 223.31,-33.54 P_OCP_CPU_12_N.4 ; P_OCP_CPU_12_N.4 224.44,-33.54 ; P_OCP_CPU_12_N.4 224.44,-34.67 ; P_OCP_CPU_12_N.4 223.31,-34.67 ; 239.04,-17.81 P_CPU_OCP_13_P.4 ; P_CPU_OCP_13_P.4 240.17,-18.94 ; P_CPU_OCP_13_P.4 240.17,-17.81 ; P_CPU_OCP_13_P.4 239.04,-18.94 ; P_BD2_CLK2_N.2 259.68,-68.86 ; P_BD2_CLK2_N.2 258.55,-69.99 ; P_BD2_CLK2_N.2 258.55,-68.86 ; P_BD2_CLK2_N.2 259.68,-69.99 ; P_OCP_CPU_14_N.2 182.07,-10.68 ; P_OCP_CPU_14_N.2 182.07,-11.81 ; P_OCP_CPU_14_N.2 180.94,-11.81 ; P_OCP_CPU_14_N.2 180.94,-10.68 ; 249.52,-12.57 P_CPU_OCP_15_P.2 ; P_CPU_OCP_15_P.2 250.65,-12.57 ; P_CPU_OCP_15_P.2 250.65,-11.44 ; P_CPU_OCP_15_P.2 249.52,-11.44 ; 235.69,-6.38 P_CPU_OCP_14_P.2 ; P_CPU_OCP_14_P.2 236.82,-7.51 ; P_CPU_OCP_14_P.2 235.69,-7.51 ; P_CPU_OCP_14_P.2 236.82,-6.38 ; P_CPU_OCP_12_N.5 247.3,-32.08 ; P_CPU_OCP_12_N.5 246.17,-32.08 ; P_CPU_OCP_12_N.5 247.3,-30.95 ; P_CPU_OCP_12_N.5 246.17,-30.95 ; P_OCP_CPU_14_N.4 178.72,-7.51 ; P_OCP_CPU_14_N.4 177.59,-6.38 ; P_OCP_CPU_14_N.4 178.72,-6.38 ; P_OCP_CPU_14_N.4 177.59,-7.51 ; 239.04,-7.51 P_CPU_OCP_14_P.3 ; P_CPU_OCP_14_P.3 240.17,-7.51 ; P_CPU_OCP_14_P.3 239.04,-6.38 ; P_CPU_OCP_14_P.3 240.17,-6.38 ; P_CPU_OCP_8_N.2 263.03,-53.81 ; P_CPU_OCP_8_N.2 261.9,-54.94 ; P_CPU_OCP_8_N.2 261.9,-53.81 ; P_CPU_OCP_8_N.2 263.03,-54.94 ; P_CPU_OCP_15_P.5 250.65,-7.14 ; P_CPU_OCP_15_P.5 250.65,-8.27 ; P_CPU_OCP_15_P.5 249.52,-7.14 ; P_CPU_OCP_15_P.5 249.52,-8.27 ; P_CPU_OCP_9_P.5 251.6,-44.78 ; P_CPU_OCP_9_P.5 250.47,-45.91 ; P_CPU_OCP_9_P.5 251.6,-45.91 ; P_CPU_OCP_9_P.5 250.47,-44.78 ; 216.18,-34.67 P_OCP_CPU_11_N.3 ; P_OCP_CPU_11_N.3 217.31,-33.54 ; P_OCP_CPU_11_N.3 217.31,-34.67 ; P_OCP_CPU_11_N.3 216.18,-33.54 ; 176.32,-70.94 P_BD2_TRIG_IN_N.5 ; P_BD2_TRIG_IN_N.5 177.45,-69.81 ; P_BD2_TRIG_IN_N.5 177.45,-70.94 ; P_BD2_TRIG_IN_N.5 176.32,-69.81 ; 227.61,-56.4 P_OCP_CPU_8_N.3 ; P_OCP_CPU_8_N.3 227.61,-57.53 ; P_OCP_CPU_8_N.3 228.74,-57.53 ; P_OCP_CPU_8_N.3 228.74,-56.4 ; P_CPU_OCP_14_P.5 236.82,-10.68 ; P_CPU_OCP_14_P.5 236.82,-11.81 ; P_CPU_OCP_14_P.5 235.69,-10.68 ; P_CPU_OCP_14_P.5 235.69,-11.81 ; P_BD2_CMTS_P.2 194.45,-70.94 ; P_BD2_CMTS_P.2 193.32,-69.81 ; P_BD2_CMTS_P.2 194.45,-69.81 ; P_BD2_CMTS_P.2 193.32,-70.94 ; P_BD2_TRIG_IN_N.2 181.75,-69.81 ; P_BD2_TRIG_IN_N.2 181.75,-70.94 ; P_BD2_TRIG_IN_N.2 180.62,-70.94 ; P_BD2_TRIG_IN_N.2 180.62,-69.81 ; 239.04,-41.8 P_CPU_OCP_10_P.4 ; P_CPU_OCP_10_P.4 240.17,-40.67 ; P_CPU_OCP_10_P.4 240.17,-41.8 ; P_CPU_OCP_10_P.4 239.04,-40.67 ; 227.61,-30.19 P_OCP_CPU_12_N.2 ; P_OCP_CPU_12_N.2 227.61,-31.32 ; P_OCP_CPU_12_N.2 228.74,-31.32 ; P_OCP_CPU_12_N.2 228.74,-30.19 ; P_OCP_CPU_8_N.5 224.44,-53.05 ; P_OCP_CPU_8_N.5 223.31,-53.05 ; P_OCP_CPU_8_N.5 223.31,-54.18 ; P_OCP_CPU_8_N.5 224.44,-54.18 ; 200.45,-21.16 P_OCP_CPU_10_P.2 ; P_OCP_CPU_10_P.2 200.45,-22.29 ; P_OCP_CPU_10_P.2 201.58,-22.29 ; P_OCP_CPU_10_P.2 201.58,-21.16 ; 180.62,-73.16 P_BD2_TRIG_IN_N.3 ; P_BD2_TRIG_IN_N.3 181.75,-74.29 ; P_BD2_TRIG_IN_N.3 181.75,-73.16 ; P_BD2_TRIG_IN_N.3 180.62,-74.29 ; 246.17,-7.14 P_CPU_OCP_15_P.4 ; P_CPU_OCP_15_P.4 247.3,-7.14 ; P_CPU_OCP_15_P.4 246.17,-8.27 ; P_CPU_OCP_15_P.4 247.3,-8.27 ; 246.17,-58.29 P_CPU_OCP_9_N.4 ; P_CPU_OCP_9_N.4 246.17,-57.16 ; P_CPU_OCP_9_N.4 247.3,-58.29 ; P_CPU_OCP_9_N.4 247.3,-57.16 ; P_CPU_OCP_10_P.2 235.87,-44.02 ; P_CPU_OCP_10_P.2 235.87,-45.15 ; P_CPU_OCP_10_P.2 234.74,-44.02 ; P_CPU_OCP_10_P.2 234.74,-45.15 ; P_OCP_CPU_14_P.3 194.45,-7.51 ; P_OCP_CPU_14_P.3 193.32,-7.51 ; P_OCP_CPU_14_P.3 193.32,-6.38 ; P_OCP_CPU_14_P.3 194.45,-6.38 ; P_BD2_TRIG_IN_P.5 181.75,-61.91 ; P_BD2_TRIG_IN_P.5 180.62,-60.78 ; P_BD2_TRIG_IN_P.5 181.75,-60.78 ; P_BD2_TRIG_IN_P.5 180.62,-61.91 ; 189.02,-73.16 P_BD2_CMTS_P.4 ; P_BD2_CMTS_P.4 190.15,-74.29 ; P_BD2_CMTS_P.4 190.15,-73.16 ; P_BD2_CMTS_P.4 189.02,-74.29 ; P_CPU_OCP_14_P.4 240.17,-10.68 ; P_CPU_OCP_14_P.4 240.17,-11.81 ; P_CPU_OCP_14_P.4 239.04,-10.68 ; P_CPU_OCP_14_P.4 239.04,-11.81 ; 246.17,-41.43 P_CPU_OCP_9_P.3 ; P_CPU_OCP_9_P.3 247.3,-41.43 ; P_CPU_OCP_9_P.3 247.3,-42.56 ; P_CPU_OCP_9_P.3 246.17,-42.56 ; P_OCP_CPU_9_N.2 217.31,-53.05 ; P_OCP_CPU_9_N.2 217.31,-54.18 ; P_OCP_CPU_9_N.2 216.18,-54.18 ; P_OCP_CPU_9_N.2 216.18,-53.05 ; 227.61,-18.94 P_OCP_CPU_12_P.4 ; P_OCP_CPU_12_P.4 227.61,-17.81 ; P_OCP_CPU_12_P.4 228.74,-17.81 ; P_OCP_CPU_12_P.4 228.74,-18.94 ; 246.17,-73.16 P_BD2_CLK2_P.3 ; P_BD2_CLK2_P.3 247.3,-73.16 ; P_BD2_CLK2_P.3 246.17,-74.29 ; P_BD2_CLK2_P.3 247.3,-74.29 ; P_BD2_CLK0_P.5 227.79,-69.99 ; P_BD2_CLK0_P.5 227.79,-68.86 ; P_BD2_CLK0_P.5 226.66,-69.99 ; P_BD2_CLK0_P.5 226.66,-68.86 ; P_BD2_CLK2_N.5 259.68,-74.29 ; P_BD2_CLK2_N.5 258.55,-74.29 ; P_BD2_CLK2_N.5 259.68,-73.16 ; P_BD2_CLK2_N.5 258.55,-73.16 ; 234.74,-18.94 P_CPU_OCP_13_P.3 ; P_CPU_OCP_13_P.3 235.87,-17.81 ; P_CPU_OCP_13_P.3 234.74,-17.81 ; P_CPU_OCP_13_P.3 235.87,-18.94 ; 211.88,-21.16 P_OCP_CPU_11_P.2 ; P_OCP_CPU_11_P.2 213.01,-21.16 ; P_OCP_CPU_11_P.2 211.88,-22.29 ; P_OCP_CPU_11_P.2 213.01,-22.29 ; P_OCP_CPU_10_N.3 205.88,-33.54 ; P_OCP_CPU_10_N.3 204.75,-33.54 ; P_OCP_CPU_10_N.3 204.75,-34.67 ; P_OCP_CPU_10_N.3 205.88,-34.67 ; 250.47,-35.43 P_CPU_OCP_12_N.3 ; P_CPU_OCP_12_N.3 251.6,-34.3 ; P_CPU_OCP_12_N.3 251.6,-35.43 ; P_CPU_OCP_12_N.3 250.47,-34.3 ; P_BD2_TRIG_IN_P.2 177.45,-61.91 ; P_BD2_TRIG_IN_P.2 177.45,-60.78 ; P_BD2_TRIG_IN_P.2 176.32,-61.91 ; P_BD2_TRIG_IN_P.2 176.32,-60.78 ; P_OCP_CPU_12_P.2 224.44,-22.29 ; P_OCP_CPU_12_P.2 223.31,-22.29 ; P_OCP_CPU_12_P.2 224.44,-21.16 ; P_OCP_CPU_12_P.2 223.31,-21.16 ; 189.02,-60.78 P_BD2_CMTS_N.2 ; P_BD2_CMTS_N.2 190.15,-61.91 ; P_BD2_CMTS_N.2 189.02,-61.91 ; P_BD2_CMTS_N.2 190.15,-60.78 ; 239.04,-34.67 P_CPU_OCP_13_N.3 ; P_CPU_OCP_13_N.3 240.17,-34.67 ; P_CPU_OCP_13_N.3 239.04,-33.54 ; P_CPU_OCP_13_N.3 240.17,-33.54 ; 193.32,-73.16 P_BD2_CMTS_P.3 ; P_BD2_CMTS_P.3 194.45,-74.29 ; P_BD2_CMTS_P.3 193.32,-74.29 ; P_BD2_CMTS_P.3 194.45,-73.16 ; 204.75,-40.67 BD2_P_OCP_CPU_0_P.4 ; BD2_P_OCP_CPU_0_P.4 204.75,-41.8 ; BD2_P_OCP_CPU_0_P.4 205.88,-40.67 ; BD2_P_OCP_CPU_0_P.4 205.88,-41.8 ; 258.55,-7.14 P_CPU_OCP_15_N.2 ; P_CPU_OCP_15_N.2 259.68,-7.14 ; P_CPU_OCP_15_N.2 258.55,-8.27 ; P_CPU_OCP_15_N.2 259.68,-8.27 ; 189.97,-22.11 P_OCP_CPU_13_N.5 ; P_OCP_CPU_13_N.5 191.1,-23.24 ; P_OCP_CPU_13_N.5 189.97,-23.24 ; P_OCP_CPU_13_N.5 191.1,-22.11 ; 227.61,-45.15 P_OCP_CPU_8_P.5 ; P_OCP_CPU_8_P.5 228.74,-44.02 ; P_OCP_CPU_8_P.5 227.61,-44.02 ; P_OCP_CPU_8_P.5 228.74,-45.15 ; P_OCP_CPU_10_N.2 205.88,-30.19 ; P_OCP_CPU_10_N.2 205.88,-31.32 ; P_OCP_CPU_10_N.2 204.75,-31.32 ; P_OCP_CPU_10_N.2 204.75,-30.19 ; P_OCP_CPU_13_P.5 182.07,-17.81 ; P_OCP_CPU_13_P.5 180.94,-17.81 ; P_OCP_CPU_13_P.5 182.07,-18.94 ; P_OCP_CPU_13_P.5 180.94,-18.94 ; P_OCP_CPU_13_N.2 191.1,-17.81 ; P_OCP_CPU_13_N.2 191.1,-18.94 ; P_OCP_CPU_13_N.2 189.97,-17.81 ; P_OCP_CPU_13_N.2 189.97,-18.94 ; P_BD2_TRIG_IN_N.4 177.45,-74.29 ; P_BD2_TRIG_IN_N.4 176.32,-74.29 ; P_BD2_TRIG_IN_N.4 176.32,-73.16 ; P_BD2_TRIG_IN_N.4 177.45,-73.16 ; P_CPU_OCP_10_N.3 240.17,-56.4 ; P_CPU_OCP_10_N.3 239.04,-57.53 ; P_CPU_OCP_10_N.3 240.17,-57.53 ; P_CPU_OCP_10_N.3 239.04,-56.4 ; 204.75,-18.94 P_OCP_CPU_10_P.4 ; P_OCP_CPU_10_P.4 205.88,-18.94 ; P_OCP_CPU_10_P.4 204.75,-17.81 ; P_OCP_CPU_10_P.4 205.88,-17.81 ; 226.66,-7.51 P_CPU_OCP_14_N.5 ; P_CPU_OCP_14_N.5 226.66,-6.38 ; P_CPU_OCP_14_N.5 227.79,-7.51 ; P_CPU_OCP_14_N.5 227.79,-6.38 ; 250.47,-18.57 P_CPU_OCP_12_P.4 ; P_CPU_OCP_12_P.4 251.6,-18.57 ; P_CPU_OCP_12_P.4 250.47,-19.7 ; P_CPU_OCP_12_P.4 251.6,-19.7 ; P_OCP_CPU_13_N.3 194.45,-18.94 ; P_OCP_CPU_13_N.3 194.45,-17.81 ; P_OCP_CPU_13_N.3 193.32,-17.81 ; P_OCP_CPU_13_N.3 193.32,-18.94 ; 193.04,-45.39 P7.2 ; P7.2 194.5,-43.92 ; P7.2 194.5,-45.39 ; P7.2 193.04,-43.92 ; P_CPU_OCP_9_P.2 247.3,-45.91 ; P_CPU_OCP_9_P.2 247.3,-44.78 ; P_CPU_OCP_9_P.2 246.17,-45.91 ; P_CPU_OCP_9_P.2 246.17,-44.78 ; 216.18,-18.94 P_OCP_CPU_11_P.4 ; P_OCP_CPU_11_P.4 216.18,-17.81 ; P_OCP_CPU_11_P.4 217.31,-18.94 ; P_OCP_CPU_11_P.4 217.31,-17.81 ; 211.88,-57.53 P_OCP_CPU_9_N.4 ; P_OCP_CPU_9_N.4 213.01,-57.53 ; P_OCP_CPU_9_N.4 213.01,-56.4 ; P_OCP_CPU_9_N.4 211.88,-56.4 ; P_OCP_CPU_15_N.2 204.93,-11.81 ; P_OCP_CPU_15_N.2 204.93,-10.68 ; P_OCP_CPU_15_N.2 203.8,-10.68 ; P_OCP_CPU_15_N.2 203.8,-11.81 ; 216.18,-69.99 P_BD2_CLK1_N.3 ; P_BD2_CLK1_N.3 217.31,-69.99 ; P_BD2_CLK1_N.3 217.31,-68.86 ; P_BD2_CLK1_N.3 216.18,-68.86 ; BD2_P_OCP_CPU_0_N.2 205.88,-53.05 ; BD2_P_OCP_CPU_0_N.2 205.88,-54.18 ; BD2_P_OCP_CPU_0_N.2 204.75,-53.05 ; BD2_P_OCP_CPU_0_N.2 204.75,-54.18 ; 203.8,-7.51 P_OCP_CPU_15_N.5 ; P_OCP_CPU_15_N.5 204.93,-7.51 ; P_OCP_CPU_15_N.5 203.8,-6.38 ; P_OCP_CPU_15_N.5 204.93,-6.38 ; P_OCP_CPU_9_P.2 213.01,-44.02 ; P_OCP_CPU_9_P.2 211.88,-44.02 ; P_OCP_CPU_9_P.2 213.01,-45.15 ; P_OCP_CPU_9_P.2 211.88,-45.15 ; P_BD2_CLK0_P.4 224.44,-68.86 ; P_BD2_CLK0_P.4 223.31,-69.99 ; P_BD2_CLK0_P.4 224.44,-69.99 ; P_BD2_CLK0_P.4 223.31,-68.86 ; P_CPU_OCP_14_N.2 227.79,-11.81 ; P_CPU_OCP_14_N.2 226.66,-11.81 ; P_CPU_OCP_14_N.2 226.66,-10.68 ; P_CPU_OCP_14_N.2 227.79,-10.68 ; P_CPU_OCP_15_N.4 263.03,-11.44 ; P_CPU_OCP_15_N.4 261.9,-11.44 ; P_CPU_OCP_15_N.4 263.03,-12.57 ; P_CPU_OCP_15_N.4 261.9,-12.57 ; P_BD2_CLK1_N.4 217.31,-73.16 ; P_BD2_CLK1_N.4 216.18,-74.29 ; P_BD2_CLK1_N.4 217.31,-74.29 ; P_BD2_CLK1_N.4 216.18,-73.16 ; 223.31,-40.67 P_OCP_CPU_8_P.3 ; P_OCP_CPU_8_P.3 224.44,-40.67 ; P_OCP_CPU_8_P.3 223.31,-41.8 ; P_OCP_CPU_8_P.3 224.44,-41.8 ; 200.45,-53.05 BD2_P_OCP_CPU_0_N.5 ; BD2_P_OCP_CPU_0_N.5 201.58,-54.18 ; BD2_P_OCP_CPU_0_N.5 201.58,-53.05 ; BD2_P_OCP_CPU_0_N.5 200.45,-54.18 ; P_BD2_CLK2_P.4 247.3,-68.86 ; P_BD2_CLK2_P.4 246.17,-68.86 ; P_BD2_CLK2_P.4 246.17,-69.99 ; P_BD2_CLK2_P.4 247.3,-69.99 ; P_CPU_OCP_8_N.5 258.73,-53.81 ; P_CPU_OCP_8_N.5 257.6,-54.94 ; P_CPU_OCP_8_N.5 258.73,-54.94 ; P_CPU_OCP_8_N.5 257.6,-53.81 ; 261.9,-45.91 P_CPU_OCP_8_P.5 ; P_CPU_OCP_8_P.5 261.9,-44.78 ; P_CPU_OCP_8_P.5 263.03,-45.91 ; P_CPU_OCP_8_P.5 263.03,-44.78 ; 261.9,-57.16 P_CPU_OCP_8_N.3 ; P_CPU_OCP_8_N.3 261.9,-58.29 ; P_CPU_OCP_8_N.3 263.03,-57.16 ; P_CPU_OCP_8_N.3 263.03,-58.29 ; P_CPU_OCP_12_P.3 247.3,-18.57 ; P_CPU_OCP_12_P.3 246.17,-18.57 ; P_CPU_OCP_12_P.3 246.17,-19.7 ; P_CPU_OCP_12_P.3 247.3,-19.7 ; P_OCP_CPU_9_P.3 213.01,-40.67 ; P_OCP_CPU_9_P.3 213.01,-41.8 ; P_OCP_CPU_9_P.3 211.88,-40.67 ; P_OCP_CPU_9_P.3 211.88,-41.8 ; 200.45,-33.54 P_OCP_CPU_10_N.4 ; P_OCP_CPU_10_N.4 201.58,-33.54 ; P_OCP_CPU_10_N.4 200.45,-34.67 ; P_OCP_CPU_10_N.4 201.58,-34.67 ; P_OCP_CPU_11_N.5 213.01,-31.32 ; P_OCP_CPU_11_N.5 211.88,-31.32 ; P_OCP_CPU_11_N.5 211.88,-30.19 ; P_OCP_CPU_11_N.5 213.01,-30.19 ; P_OCP_CPU_12_P.3 224.44,-18.94 ; P_OCP_CPU_12_P.3 224.44,-17.81 ; P_OCP_CPU_12_P.3 223.31,-17.81 ; P_OCP_CPU_12_P.3 223.31,-18.94 ; P_CPU_OCP_12_P.2 247.3,-23.05 ; P_CPU_OCP_12_P.2 246.17,-21.92 ; P_CPU_OCP_12_P.2 246.17,-23.05 ; P_CPU_OCP_12_P.2 247.3,-21.92 ; P_OCP_CPU_15_P.3 217.31,-6.38 ; P_OCP_CPU_15_P.3 216.18,-6.38 ; P_OCP_CPU_15_P.3 216.18,-7.51 ; P_OCP_CPU_15_P.3 217.31,-7.51 ; P_CPU_OCP_13_P.2 235.87,-22.29 ; P_CPU_OCP_13_P.2 234.74,-21.16 ; P_CPU_OCP_13_P.2 234.74,-22.29 ; P_CPU_OCP_13_P.2 235.87,-21.16 ; 188.59,-43.92 P8.2 ; P8.2 190.06,-43.92 ; P8.2 188.59,-45.39 ; P8.2 190.06,-45.39 ; P_BD2_CLK0_N.5 236.82,-73.16 ; P_BD2_CLK0_N.5 235.69,-73.16 ; P_BD2_CLK0_N.5 235.69,-74.29 ; P_BD2_CLK0_N.5 236.82,-74.29 ; 204.75,-57.53 BD2_P_OCP_CPU_0_N.3 ; BD2_P_OCP_CPU_0_N.3 205.88,-57.53 ; BD2_P_OCP_CPU_0_N.3 205.88,-56.4 ; BD2_P_OCP_CPU_0_N.3 204.75,-56.4 ; 180.94,-6.38 P_OCP_CPU_14_N.5 ; P_OCP_CPU_14_N.5 182.07,-6.38 ; P_OCP_CPU_14_N.5 180.94,-7.51 ; P_OCP_CPU_14_N.5 182.07,-7.51 ; 223.31,-31.32 P_OCP_CPU_12_N.5 ; P_OCP_CPU_12_N.5 223.31,-30.19 ; P_OCP_CPU_12_N.5 224.44,-30.19 ; P_OCP_CPU_12_N.5 224.44,-31.32 ; P_BD2_CLK2_P.5 250.65,-68.86 ; P_BD2_CLK2_P.5 249.52,-68.86 ; P_BD2_CLK2_P.5 249.52,-69.99 ; P_BD2_CLK2_P.5 250.65,-69.99 ; BD2_P_OCP_CPU_0_N.4 201.58,-56.4 ; BD2_P_OCP_CPU_0_N.4 200.45,-56.4 ; BD2_P_OCP_CPU_0_N.4 201.58,-57.53 ; BD2_P_OCP_CPU_0_N.4 200.45,-57.53 ; P_OCP_CPU_11_N.2 217.31,-30.19 ; P_OCP_CPU_11_N.2 216.18,-31.32 ; P_OCP_CPU_11_N.2 217.31,-31.32 ; P_OCP_CPU_11_N.2 216.18,-30.19 ; P_CPU_OCP_11_N.5 258.73,-30.95 ; P_CPU_OCP_11_N.5 257.6,-32.08 ; P_CPU_OCP_11_N.5 257.6,-30.95 ; P_CPU_OCP_11_N.5 258.73,-32.08 ; P_OCP_CPU_15_P.2 213.96,-6.38 ; P_OCP_CPU_15_P.2 213.96,-7.51 ; P_OCP_CPU_15_P.2 212.83,-7.51 ; P_OCP_CPU_15_P.2 212.83,-6.38 ; P_CPU_OCP_10_N.4 235.87,-56.4 ; P_CPU_OCP_10_N.4 234.74,-56.4 ; P_CPU_OCP_10_N.4 235.87,-57.53 ; P_CPU_OCP_10_N.4 234.74,-57.53 ; P_CPU_OCP_8_P.4 263.03,-41.43 ; P_CPU_OCP_8_P.4 263.03,-42.56 ; P_CPU_OCP_8_P.4 261.9,-41.43 ; P_CPU_OCP_8_P.4 261.9,-42.56 ; 177.59,-17.81 P_OCP_CPU_13_P.4 ; P_OCP_CPU_13_P.4 178.72,-17.81 ; P_OCP_CPU_13_P.4 178.72,-18.94 ; P_OCP_CPU_13_P.4 177.59,-18.94 ; 180.94,-22.11 P_OCP_CPU_13_P.2 ; P_OCP_CPU_13_P.2 180.94,-23.24 ; P_OCP_CPU_13_P.2 182.07,-22.11 ; P_OCP_CPU_13_P.2 182.07,-23.24 ; P_CPU_OCP_8_N.4 258.73,-58.29 ; P_CPU_OCP_8_N.4 257.6,-58.29 ; P_CPU_OCP_8_N.4 257.6,-57.16 ; P_CPU_OCP_8_N.4 258.73,-57.16 ; P_OCP_CPU_14_N.3 178.72,-10.68 ; P_OCP_CPU_14_N.3 177.59,-11.81 ; P_OCP_CPU_14_N.3 178.72,-11.81 ; P_OCP_CPU_14_N.3 177.59,-10.68 ; P_OCP_CPU_9_P.5 217.31,-44.02 ; P_OCP_CPU_9_P.5 216.18,-44.02 ; P_OCP_CPU_9_P.5 217.31,-45.15 ; P_OCP_CPU_9_P.5 216.18,-45.15 ; 234.74,-34.67 P_CPU_OCP_13_N.4 ; P_CPU_OCP_13_N.4 235.87,-34.67 ; P_CPU_OCP_13_N.4 235.87,-33.54 ; P_CPU_OCP_13_N.4 234.74,-33.54 ; P_BD2_CMTS_N.4 194.45,-58.56 ; P_BD2_CMTS_N.4 193.32,-57.43 ; P_BD2_CMTS_N.4 193.32,-58.56 ; P_BD2_CMTS_N.4 194.45,-57.43 ; P_CPU_OCP_13_N.5 235.87,-31.32 ; P_CPU_OCP_13_N.5 234.74,-31.32 ; P_CPU_OCP_13_N.5 235.87,-30.19 ; P_CPU_OCP_13_N.5 234.74,-30.19 ; 250.47,-58.29 P_CPU_OCP_9_N.3 ; P_CPU_OCP_9_N.3 251.6,-58.29 ; P_CPU_OCP_9_N.3 251.6,-57.16 ; P_CPU_OCP_9_N.3 250.47,-57.16 ; P_OCP_CPU_8_N.4 224.44,-56.4 ; P_OCP_CPU_8_N.4 223.31,-56.4 ; P_OCP_CPU_8_N.4 223.31,-57.53 ; P_OCP_CPU_8_N.4 224.44,-57.53 ; 239.04,-45.15 P_CPU_OCP_10_P.5 ; P_CPU_OCP_10_P.5 239.04,-44.02 ; P_CPU_OCP_10_P.5 240.17,-45.15 ; P_CPU_OCP_10_P.5 240.17,-44.02 ; 261.9,-34.3 P_CPU_OCP_11_N.3 ; P_CPU_OCP_11_N.3 261.9,-35.43 ; P_CPU_OCP_11_N.3 263.03,-34.3 ; P_CPU_OCP_11_N.3 263.03,-35.43 ; P_BD2_CLK0_N.2 236.82,-68.86 ; P_BD2_CLK0_N.2 235.69,-68.86 ; P_BD2_CLK0_N.2 236.82,-69.99 ; P_BD2_CLK0_N.2 235.69,-69.99 ; 261.9,-68.86 P_BD2_CLK2_N.3 ; P_BD2_CLK2_N.3 261.9,-69.99 ; P_BD2_CLK2_N.3 263.03,-68.86 ; P_BD2_CLK2_N.3 263.03,-69.99 ; 223.31,-73.16 P_BD2_CLK0_P.3 ; P_BD2_CLK0_P.3 224.44,-74.29 ; P_BD2_CLK0_P.3 224.44,-73.16 ; P_BD2_CLK0_P.3 223.31,-74.29 ; P_CPU_OCP_15_N.5 259.68,-12.57 ; P_CPU_OCP_15_N.5 259.68,-11.44 ; P_CPU_OCP_15_N.5 258.55,-11.44 ; P_CPU_OCP_15_N.5 258.55,-12.57 ; P_CPU_OCP_15_P.3 247.3,-12.57 ; P_CPU_OCP_15_P.3 247.3,-11.44 ; P_CPU_OCP_15_P.3 246.17,-12.57 ; P_CPU_OCP_15_P.3 246.17,-11.44 ; 239.04,-53.05 P_CPU_OCP_10_N.2 ; P_CPU_OCP_10_N.2 240.17,-54.18 ; P_CPU_OCP_10_N.2 240.17,-53.05 ; P_CPU_OCP_10_N.2 239.04,-54.18 ; 257.6,-34.3 P_CPU_OCP_11_N.4 ; P_CPU_OCP_11_N.4 258.73,-35.43 ; P_CPU_OCP_11_N.4 257.6,-35.43 ; P_CPU_OCP_11_N.4 258.73,-34.3 ; P_OCP_CPU_10_P.3 201.58,-18.94 ; P_OCP_CPU_10_P.3 201.58,-17.81 ; P_OCP_CPU_10_P.3 200.45,-17.81 ; P_OCP_CPU_10_P.3 200.45,-18.94 ; P_OCP_CPU_14_P.5 191.1,-11.81 ; P_OCP_CPU_14_P.5 191.1,-10.68 ; P_OCP_CPU_14_P.5 189.97,-10.68 ; P_OCP_CPU_14_P.5 189.97,-11.81 ; P_OCP_CPU_11_P.3 213.01,-18.94 ; P_OCP_CPU_11_P.3 211.88,-17.81 ; P_OCP_CPU_11_P.3 211.88,-18.94 ; P_OCP_CPU_11_P.3 213.01,-17.81 ; P_OCP_CPU_15_N.3 201.58,-11.81 ; P_OCP_CPU_15_N.3 200.45,-11.81 ; P_OCP_CPU_15_N.3 200.45,-10.68 ; P_OCP_CPU_15_N.3 201.58,-10.68 ; 200.45,-69.99 P_BD2_CLK1_P.4 ; P_BD2_CLK1_P.4 201.58,-68.86 ; P_BD2_CLK1_P.4 201.58,-69.99 ; P_BD2_CLK1_P.4 200.45,-68.86 ; 227.61,-54.18 P_OCP_CPU_8_N.2 ; P_OCP_CPU_8_N.2 227.61,-53.05 ; P_OCP_CPU_8_N.2 228.74,-53.05 ; P_OCP_CPU_8_N.2 228.74,-54.18 ; P_BD2_CLK1_P.5 204.93,-68.86 ; P_BD2_CLK1_P.5 204.93,-69.99 ; P_BD2_CLK1_P.5 203.8,-69.99 ; P_BD2_CLK1_P.5 203.8,-68.86 ; 239.04,-21.16 P_CPU_OCP_13_P.5 ; P_CPU_OCP_13_P.5 239.04,-22.29 ; P_CPU_OCP_13_P.5 240.17,-22.29 ; P_CPU_OCP_13_P.5 240.17,-21.16 ; P_OCP_CPU_11_P.5 217.31,-21.16 ; P_OCP_CPU_11_P.5 216.18,-21.16 ; P_OCP_CPU_11_P.5 217.31,-22.29 ; P_OCP_CPU_11_P.5 216.18,-22.29 ; 176.32,-57.43 P_BD2_TRIG_IN_P.3 ; P_BD2_TRIG_IN_P.3 177.45,-58.56 ; P_BD2_TRIG_IN_P.3 177.45,-57.43 ; P_BD2_TRIG_IN_P.3 176.32,-58.56 ; 249.52,-74.29 P_BD2_CLK2_P.2 ; P_BD2_CLK2_P.2 250.65,-74.29 ; P_BD2_CLK2_P.2 249.52,-73.16 ; P_BD2_CLK2_P.2 250.65,-73.16 ; P_OCP_CPU_14_P.4 194.45,-10.68 ; P_OCP_CPU_14_P.4 193.32,-10.68 ; P_OCP_CPU_14_P.4 194.45,-11.81 ; P_OCP_CPU_14_P.4 193.32,-11.81 ; P_CPU_OCP_11_P.2 258.73,-21.92 ; P_CPU_OCP_11_P.2 258.73,-23.05 ; P_CPU_OCP_11_P.2 257.6,-21.92 ; P_CPU_OCP_11_P.2 257.6,-23.05 ; P_OCP_CPU_9_P.4 217.31,-41.8 ; P_OCP_CPU_9_P.4 216.18,-41.8 ; P_OCP_CPU_9_P.4 217.31,-40.67 ; P_OCP_CPU_9_P.4 216.18,-40.67 ; P_BD2_CLK1_N.5 213.96,-73.16 ; P_BD2_CLK1_N.5 212.83,-73.16 ; P_BD2_CLK1_N.5 212.83,-74.29 ; P_BD2_CLK1_N.5 213.96,-74.29 ; 204.75,-45.15 BD2_P_OCP_CPU_0_P.5 ; BD2_P_OCP_CPU_0_P.5 205.88,-45.15 ; BD2_P_OCP_CPU_0_P.5 204.75,-44.02 ; BD2_P_OCP_CPU_0_P.5 205.88,-44.02 ; P_OCP_CPU_12_N.3 228.74,-34.67 ; P_OCP_CPU_12_N.3 227.61,-34.67 ; P_OCP_CPU_12_N.3 227.61,-33.54 ; P_OCP_CPU_12_N.3 228.74,-33.54 ; P_CPU_OCP_9_P.4 251.6,-41.43 ; P_CPU_OCP_9_P.4 251.6,-42.56 ; P_CPU_OCP_9_P.4 250.47,-42.56 ; P_CPU_OCP_9_P.4 250.47,-41.43 ; P_OCP_CPU_15_P.5 213.96,-10.68 ; P_OCP_CPU_15_P.5 213.96,-11.81 ; P_OCP_CPU_15_P.5 212.83,-10.68 ; P_OCP_CPU_15_P.5 212.83,-11.81 ; P_CPU_OCP_10_N.5 235.87,-53.05 ; P_CPU_OCP_10_N.5 234.74,-54.18 ; P_CPU_OCP_10_N.5 234.74,-53.05 ; P_CPU_OCP_10_N.5 235.87,-54.18 ; 257.6,-41.43 P_CPU_OCP_8_P.3 ; P_CPU_OCP_8_P.3 258.73,-42.56 ; P_CPU_OCP_8_P.3 258.73,-41.43 ; P_CPU_OCP_8_P.3 257.6,-42.56 ; BD2_P_OCP_CPU_0_P.2 201.58,-45.15 ; BD2_P_OCP_CPU_0_P.2 201.58,-44.02 ; BD2_P_OCP_CPU_0_P.2 200.45,-44.02 ; BD2_P_OCP_CPU_0_P.2 200.45,-45.15 ; P_BD2_CLK0_P.2 227.79,-73.16 ; P_BD2_CLK0_P.2 226.66,-74.29 ; P_BD2_CLK0_P.2 226.66,-73.16 ; P_BD2_CLK0_P.2 227.79,-74.29 ; P_CPU_OCP_11_P.5 263.03,-23.05 ; P_CPU_OCP_11_P.5 261.9,-23.05 ; P_CPU_OCP_11_P.5 263.03,-21.92 ; P_CPU_OCP_11_P.5 261.9,-21.92 ; 200.45,-40.67 BD2_P_OCP_CPU_0_P.3 ; BD2_P_OCP_CPU_0_P.3 201.58,-41.8 ; BD2_P_OCP_CPU_0_P.3 201.58,-40.67 ; BD2_P_OCP_CPU_0_P.3 200.45,-41.8 ; P_OCP_CPU_15_N.4 201.58,-6.38 ; P_OCP_CPU_15_N.4 201.58,-7.51 ; P_OCP_CPU_15_N.4 200.45,-6.38 ; P_OCP_CPU_15_N.4 200.45,-7.51 ; P_CPU_OCP_14_N.3 224.44,-11.81 ; P_CPU_OCP_14_N.3 223.31,-11.81 ; P_CPU_OCP_14_N.3 223.31,-10.68 ; P_CPU_OCP_14_N.3 224.44,-10.68 ; P_BD2_CLK1_P.2 204.93,-74.29 ; P_BD2_CLK1_P.2 203.8,-74.29 ; P_BD2_CLK1_P.2 204.93,-73.16 ; P_BD2_CLK1_P.2 203.8,-73.16 ; 204.75,-22.29 P_OCP_CPU_10_P.5 ; P_OCP_CPU_10_P.5 205.88,-21.16 ; P_OCP_CPU_10_P.5 204.75,-21.16 ; P_OCP_CPU_10_P.5 205.88,-22.29 ; 216.18,-56.4 P_OCP_CPU_9_N.3 ; P_OCP_CPU_9_N.3 216.18,-57.53 ; P_OCP_CPU_9_N.3 217.31,-56.4 ; P_OCP_CPU_9_N.3 217.31,-57.53 ; P_CPU_OCP_10_P.3 235.87,-41.8 ; P_CPU_OCP_10_P.3 235.87,-40.67 ; P_CPU_OCP_10_P.3 234.74,-40.67 ; P_CPU_OCP_10_P.3 234.74,-41.8 ; 212.83,-68.86 P_BD2_CLK1_N.2 ; P_BD2_CLK1_N.2 213.96,-69.99 ; P_BD2_CLK1_N.2 212.83,-69.99 ; P_BD2_CLK1_N.2 213.96,-68.86 ; P_OCP_CPU_14_P.2 191.1,-7.51 ; P_OCP_CPU_14_P.2 189.97,-7.51 ; P_OCP_CPU_14_P.2 189.97,-6.38 ; P_OCP_CPU_14_P.2 191.1,-6.38 ; 246.17,-34.3 P_CPU_OCP_12_N.4 ; P_CPU_OCP_12_N.4 246.17,-35.43 ; P_CPU_OCP_12_N.4 247.3,-34.3 ; P_CPU_OCP_12_N.4 247.3,-35.43 ; P_CPU_OCP_15_N.3 263.03,-7.14 ; P_CPU_OCP_15_N.3 263.03,-8.27 ; P_CPU_OCP_15_N.3 261.9,-8.27 ; P_CPU_OCP_15_N.3 261.9,-7.14 ; 261.9,-30.95 P_CPU_OCP_11_N.2 ; P_CPU_OCP_11_N.2 263.03,-32.08 ; P_CPU_OCP_11_N.2 263.03,-30.95 ; P_CPU_OCP_11_N.2 261.9,-32.08 ; 239.04,-73.16 P_BD2_CLK0_N.4 ; P_BD2_CLK0_N.4 239.04,-74.29 ; P_BD2_CLK0_N.4 240.17,-73.16 ; P_BD2_CLK0_N.4 240.17,-74.29 ; P_BD2_CLK0_N.3 240.17,-69.99 ; P_BD2_CLK0_N.3 239.04,-69.99 ; P_BD2_CLK0_N.3 240.17,-68.86 ; P_BD2_CLK0_N.3 239.04,-68.86 ; 216.18,-11.81 P_OCP_CPU_15_P.4 ; P_OCP_CPU_15_P.4 216.18,-10.68 ; P_OCP_CPU_15_P.4 217.31,-10.68 ; P_OCP_CPU_15_P.4 217.31,-11.81 ; 250.47,-53.81 P_CPU_OCP_9_N.2 ; P_CPU_OCP_9_N.2 251.6,-54.94 ; P_CPU_OCP_9_N.2 250.47,-54.94 ; P_CPU_OCP_9_N.2 251.6,-53.81 ; P_BD2_CLK1_P.3 201.58,-73.16 ; P_BD2_CLK1_P.3 200.45,-74.29 ; P_BD2_CLK1_P.3 201.58,-74.29 ; P_BD2_CLK1_P.3 200.45,-73.16 ; P_OCP_CPU_8_P.2 224.44,-45.15 ; P_OCP_CPU_8_P.2 224.44,-44.02 ; P_OCP_CPU_8_P.2 223.31,-44.02 ; P_OCP_CPU_8_P.2 223.31,-45.15 ; P_CPU_OCP_12_P.5 251.6,-21.92 ; P_CPU_OCP_12_P.5 250.47,-23.05 ; P_CPU_OCP_12_P.5 251.6,-23.05 ; P_CPU_OCP_12_P.5 250.47,-21.92 ; P_OCP_CPU_11_N.4 213.01,-34.67 ; P_OCP_CPU_11_N.4 213.01,-33.54 ; P_OCP_CPU_11_N.4 211.88,-33.54 ; P_OCP_CPU_11_N.4 211.88,-34.67 ; 257.6,-45.91 P_CPU_OCP_8_P.2 ; P_CPU_OCP_8_P.2 258.73,-45.91 ; P_CPU_OCP_8_P.2 257.6,-44.78 ; P_CPU_OCP_8_P.2 258.73,-44.78 ; P_BD2_CMTS_P.5 190.15,-70.94 ; P_BD2_CMTS_P.5 189.02,-69.81 ; P_BD2_CMTS_P.5 190.15,-69.81 ; P_BD2_CMTS_P.5 189.02,-70.94 ; P_OCP_CPU_10_N.5 201.58,-30.19 ; P_OCP_CPU_10_N.5 200.45,-31.32 ; P_OCP_CPU_10_N.5 201.58,-31.32 ; P_OCP_CPU_10_N.5 200.45,-30.19 ; P_CPU_OCP_13_N.2 240.17,-30.19 ; P_CPU_OCP_13_N.2 239.04,-30.19 ; P_CPU_OCP_13_N.2 240.17,-31.32 ; P_CPU_OCP_13_N.2 239.04,-31.32 ; P_CPU_OCP_14_N.4 224.44,-6.38 ; P_CPU_OCP_14_N.4 223.31,-7.51 ; P_CPU_OCP_14_N.4 223.31,-6.38 ; P_CPU_OCP_14_N.4 224.44,-7.51 ; P_CPU_OCP_12_N.2 251.6,-32.08 ; P_CPU_OCP_12_N.2 250.47,-30.95 ; P_CPU_OCP_12_N.2 250.47,-32.08 ; P_CPU_OCP_12_N.2 251.6,-30.95 ; 189.02,-57.43 P_BD2_CMTS_N.3 ; P_BD2_CMTS_N.3 189.02,-58.56 ; P_BD2_CMTS_N.3 190.15,-57.43 ; P_BD2_CMTS_N.3 190.15,-58.56 ; P_CPU_OCP_11_P.3 258.73,-19.7 ; P_CPU_OCP_11_P.3 257.6,-18.57 ; P_CPU_OCP_11_P.3 257.6,-19.7 ; P_CPU_OCP_11_P.3 258.73,-18.57 ; P_OCP_CPU_8_P.4 228.74,-41.8 ; P_OCP_CPU_8_P.4 228.74,-40.67 ; P_OCP_CPU_8_P.4 227.61,-41.8 ; P_OCP_CPU_8_P.4 227.61,-40.67 ; 193.32,-23.24 P_OCP_CPU_13_N.4 ; P_OCP_CPU_13_N.4 194.45,-23.24 ; P_OCP_CPU_13_N.4 193.32,-22.11 ; P_OCP_CPU_13_N.4 194.45,-22.11 ; P15.2 185.49,-52.5 ; P15.2 184.02,-51.03 ; P15.2 185.49,-51.03 ; P15.2 184.02,-52.5 ; P_OCP_CPU_9_N.5 213.01,-53.05 ; P_OCP_CPU_9_N.5 211.88,-54.18 ; P_OCP_CPU_9_N.5 213.01,-54.18 ; P_OCP_CPU_9_N.5 211.88,-53.05 ; 261.9,-73.16 P_BD2_CLK2_N.4 ; P_BD2_CLK2_N.4 263.03,-73.16 ; P_BD2_CLK2_N.4 263.03,-74.29 ; P_BD2_CLK2_N.4 261.9,-74.29 ; P_CPU_OCP_9_N.5 247.3,-54.94 ; P_CPU_OCP_9_N.5 247.3,-53.81 ; P_CPU_OCP_9_N.5 246.17,-54.94 ; P_CPU_OCP_9_N.5 246.17,-53.81 ; 227.61,-21.16 P_OCP_CPU_12_P.5 ; P_OCP_CPU_12_P.5 227.61,-22.29 ; P_OCP_CPU_12_P.5 228.74,-22.29 ; P_OCP_CPU_12_P.5 228.74,-21.16 ; P_BD2_TRIG_IN_P.4 181.75,-58.56 ; P_BD2_TRIG_IN_P.4 181.75,-57.43 ; P_BD2_TRIG_IN_P.4 180.62,-58.56 ; P_BD2_TRIG_IN_P.4 180.62,-57.43 ; 177.59,-23.24 P_OCP_CPU_13_P.3 ; P_OCP_CPU_13_P.3 178.72,-22.11 ; P_OCP_CPU_13_P.3 177.59,-22.11 ; P_OCP_CPU_13_P.3 178.72,-23.24 ; 261.9,-19.7 P_CPU_OCP_11_P.4 ; P_CPU_OCP_11_P.4 263.03,-19.7 ; P_CPU_OCP_11_P.4 261.9,-18.57 ; P_CPU_OCP_11_P.4 263.03,-18.57
  GD3 w0.254: P_CPU_OCP_14_P.3 240.17,-6.38 ; P_CPU_OCP_14_P.3 239.04,-7.51 ; P_CPU_OCP_14_P.3 240.17,-7.51 ; P_CPU_OCP_14_P.3 239.04,-6.38 ; 177.59,-22.11 P_OCP_CPU_13_P.3 ; P_OCP_CPU_13_P.3 178.72,-22.11 ; P_OCP_CPU_13_P.3 178.72,-23.24 ; P_OCP_CPU_13_P.3 177.59,-23.24 ; P_BD2_CMTS_N.4 194.45,-57.43 ; P_BD2_CMTS_N.4 193.32,-57.43 ; P_BD2_CMTS_N.4 193.32,-58.56 ; P_BD2_CMTS_N.4 194.45,-58.56 ; P_OCP_CPU_11_N.4 213.01,-33.54 ; P_OCP_CPU_11_N.4 211.88,-33.54 ; P_OCP_CPU_11_N.4 211.88,-34.67 ; P_OCP_CPU_11_N.4 213.01,-34.67 ; P_BD2_CLK0_N.4 240.17,-74.29 ; P_BD2_CLK0_N.4 240.17,-73.16 ; P_BD2_CLK0_N.4 239.04,-74.29 ; P_BD2_CLK0_N.4 239.04,-73.16 ; P_CPU_OCP_12_N.2 251.6,-30.95 ; P_CPU_OCP_12_N.2 251.6,-32.08 ; P_CPU_OCP_12_N.2 250.47,-32.08 ; P_CPU_OCP_12_N.2 250.47,-30.95 ; 189.97,-22.11 P_OCP_CPU_13_N.5 ; P_OCP_CPU_13_N.5 191.1,-23.24 ; P_OCP_CPU_13_N.5 189.97,-23.24 ; P_OCP_CPU_13_N.5 191.1,-22.11 ; P9.2 185.61,-45.39 ; P9.2 184.15,-45.39 ; P9.2 184.15,-43.92 ; P9.2 185.61,-43.92 ; 204.75,-56.4 BD2_P_OCP_CPU_0_N.3 ; BD2_P_OCP_CPU_0_N.3 205.88,-57.53 ; BD2_P_OCP_CPU_0_N.3 204.75,-57.53 ; BD2_P_OCP_CPU_0_N.3 205.88,-56.4 ; 261.9,-19.7 P_CPU_OCP_11_P.4 ; P_CPU_OCP_11_P.4 263.03,-18.57 ; P_CPU_OCP_11_P.4 263.03,-19.7 ; P_CPU_OCP_11_P.4 261.9,-18.57 ; P_CPU_OCP_13_N.5 235.87,-30.19 ; P_CPU_OCP_13_N.5 234.74,-30.19 ; P_CPU_OCP_13_N.5 234.74,-31.32 ; P_CPU_OCP_13_N.5 235.87,-31.32 ; 246.17,-53.81 P_CPU_OCP_9_N.5 ; P_CPU_OCP_9_N.5 247.3,-53.81 ; P_CPU_OCP_9_N.5 246.17,-54.94 ; P_CPU_OCP_9_N.5 247.3,-54.94 ; 212.83,-11.81 P_OCP_CPU_15_P.5 ; P_OCP_CPU_15_P.5 212.83,-10.68 ; P_OCP_CPU_15_P.5 213.96,-10.68 ; P_OCP_CPU_15_P.5 213.96,-11.81 ; 189.97,-17.81 P_OCP_CPU_13_N.2 ; P_OCP_CPU_13_N.2 191.1,-17.81 ; P_OCP_CPU_13_N.2 191.1,-18.94 ; P_OCP_CPU_13_N.2 189.97,-18.94 ; 193.32,-74.29 P_BD2_CMTS_P.3 ; P_BD2_CMTS_P.3 194.45,-73.16 ; P_BD2_CMTS_P.3 194.45,-74.29 ; P_BD2_CMTS_P.3 193.32,-73.16 ; P_BD2_CMTS_N.5 194.45,-60.78 ; P_BD2_CMTS_N.5 193.32,-61.91 ; P_BD2_CMTS_N.5 193.32,-60.78 ; P_BD2_CMTS_N.5 194.45,-61.91 ; 177.59,-6.38 P_OCP_CPU_14_N.4 ; P_OCP_CPU_14_N.4 178.72,-7.51 ; P_OCP_CPU_14_N.4 178.72,-6.38 ; P_OCP_CPU_14_N.4 177.59,-7.51 ; 261.9,-73.16 P_BD2_CLK2_N.4 ; P_BD2_CLK2_N.4 263.03,-74.29 ; P_BD2_CLK2_N.4 263.03,-73.16 ; P_BD2_CLK2_N.4 261.9,-74.29 ; P_CPU_OCP_13_P.2 235.87,-22.29 ; P_CPU_OCP_13_P.2 234.74,-21.16 ; P_CPU_OCP_13_P.2 234.74,-22.29 ; P_CPU_OCP_13_P.2 235.87,-21.16 ; P_BD2_CLK0_N.3 240.17,-69.99 ; P_BD2_CLK0_N.3 240.17,-68.86 ; P_BD2_CLK0_N.3 239.04,-69.99 ; P_BD2_CLK0_N.3 239.04,-68.86 ; P7.2 194.5,-45.39 ; P7.2 193.04,-45.39 ; P7.2 194.5,-43.92 ; P7.2 193.04,-43.92 ; 223.31,-73.16 P_BD2_CLK0_P.3 ; P_BD2_CLK0_P.3 223.31,-74.29 ; P_BD2_CLK0_P.3 224.44,-74.29 ; P_BD2_CLK0_P.3 224.44,-73.16 ; P_OCP_CPU_11_P.4 217.31,-18.94 ; P_OCP_CPU_11_P.4 216.18,-17.81 ; P_OCP_CPU_11_P.4 217.31,-17.81 ; P_OCP_CPU_11_P.4 216.18,-18.94 ; 203.8,-11.81 P_OCP_CPU_15_N.2 ; P_OCP_CPU_15_N.2 204.93,-11.81 ; P_OCP_CPU_15_N.2 203.8,-10.68 ; P_OCP_CPU_15_N.2 204.93,-10.68 ; P_BD2_TRIG_IN_N.4 177.45,-73.16 ; P_BD2_TRIG_IN_N.4 176.32,-74.29 ; P_BD2_TRIG_IN_N.4 176.32,-73.16 ; P_BD2_TRIG_IN_N.4 177.45,-74.29 ; P_OCP_CPU_11_P.5 217.31,-22.29 ; P_OCP_CPU_11_P.5 217.31,-21.16 ; P_OCP_CPU_11_P.5 216.18,-21.16 ; P_OCP_CPU_11_P.5 216.18,-22.29 ; 200.45,-40.67 BD2_P_OCP_CPU_0_P.3 ; BD2_P_OCP_CPU_0_P.3 201.58,-40.67 ; BD2_P_OCP_CPU_0_P.3 200.45,-41.8 ; BD2_P_OCP_CPU_0_P.3 201.58,-41.8 ; 249.52,-8.27 P_CPU_OCP_15_P.5 ; P_CPU_OCP_15_P.5 250.65,-7.14 ; P_CPU_OCP_15_P.5 250.65,-8.27 ; P_CPU_OCP_15_P.5 249.52,-7.14 ; P_CPU_OCP_9_P.2 247.3,-45.91 ; P_CPU_OCP_9_P.2 246.17,-44.78 ; P_CPU_OCP_9_P.2 247.3,-44.78 ; P_CPU_OCP_9_P.2 246.17,-45.91 ; P_CPU_OCP_14_N.4 224.44,-7.51 ; P_CPU_OCP_14_N.4 223.31,-7.51 ; P_CPU_OCP_14_N.4 223.31,-6.38 ; P_CPU_OCP_14_N.4 224.44,-6.38 ; 261.9,-41.43 P_CPU_OCP_8_P.4 ; P_CPU_OCP_8_P.4 263.03,-42.56 ; P_CPU_OCP_8_P.4 261.9,-42.56 ; P_CPU_OCP_8_P.4 263.03,-41.43 ; P_BD2_CMTS_P.5 190.15,-70.94 ; P_BD2_CMTS_P.5 189.02,-70.94 ; P_BD2_CMTS_P.5 189.02,-69.81 ; P_BD2_CMTS_P.5 190.15,-69.81 ; 188.59,-45.39 P8.2 ; P8.2 188.59,-43.92 ; P8.2 190.06,-43.92 ; P8.2 190.06,-45.39 ; 239.04,-10.68 P_CPU_OCP_14_P.4 ; P_CPU_OCP_14_P.4 239.04,-11.81 ; P_CPU_OCP_14_P.4 240.17,-11.81 ; P_CPU_OCP_14_P.4 240.17,-10.68 ; 176.32,-57.43 P_BD2_TRIG_IN_P.3 ; P_BD2_TRIG_IN_P.3 177.45,-57.43 ; P_BD2_TRIG_IN_P.3 176.32,-58.56 ; P_BD2_TRIG_IN_P.3 177.45,-58.56 ; P_CPU_OCP_8_N.4 258.73,-58.29 ; P_CPU_OCP_8_N.4 257.6,-57.16 ; P_CPU_OCP_8_N.4 258.73,-57.16 ; P_CPU_OCP_8_N.4 257.6,-58.29 ; P_CPU_OCP_9_P.3 247.3,-42.56 ; P_CPU_OCP_9_P.3 247.3,-41.43 ; P_CPU_OCP_9_P.3 246.17,-41.43 ; P_CPU_OCP_9_P.3 246.17,-42.56 ; 239.04,-34.67 P_CPU_OCP_13_N.3 ; P_CPU_OCP_13_N.3 240.17,-34.67 ; P_CPU_OCP_13_N.3 240.17,-33.54 ; P_CPU_OCP_13_N.3 239.04,-33.54 ; P_BD2_CMTS_P.4 190.15,-73.16 ; P_BD2_CMTS_P.4 189.02,-74.29 ; P_BD2_CMTS_P.4 189.02,-73.16 ; P_BD2_CMTS_P.4 190.15,-74.29 ; 246.17,-19.7 P_CPU_OCP_12_P.3 ; P_CPU_OCP_12_P.3 247.3,-18.57 ; P_CPU_OCP_12_P.3 246.17,-18.57 ; P_CPU_OCP_12_P.3 247.3,-19.7 ; P_BD2_CLK2_P.3 247.3,-73.16 ; P_BD2_CLK2_P.3 247.3,-74.29 ; P_BD2_CLK2_P.3 246.17,-74.29 ; P_BD2_CLK2_P.3 246.17,-73.16 ; 235.69,-73.16 P_BD2_CLK0_N.5 ; P_BD2_CLK0_N.5 236.82,-73.16 ; P_BD2_CLK0_N.5 235.69,-74.29 ; P_BD2_CLK0_N.5 236.82,-74.29 ; 257.6,-30.95 P_CPU_OCP_11_N.5 ; P_CPU_OCP_11_N.5 258.73,-32.08 ; P_CPU_OCP_11_N.5 258.73,-30.95 ; P_CPU_OCP_11_N.5 257.6,-32.08 ; 189.02,-60.78 P_BD2_CMTS_N.2 ; P_BD2_CMTS_N.2 189.02,-61.91 ; P_BD2_CMTS_N.2 190.15,-60.78 ; P_BD2_CMTS_N.2 190.15,-61.91 ; P_CPU_OCP_15_P.3 247.3,-12.57 ; P_CPU_OCP_15_P.3 246.17,-11.44 ; P_CPU_OCP_15_P.3 247.3,-11.44 ; P_CPU_OCP_15_P.3 246.17,-12.57 ; P_OCP_CPU_12_N.4 224.44,-33.54 ; P_OCP_CPU_12_N.4 223.31,-33.54 ; P_OCP_CPU_12_N.4 224.44,-34.67 ; P_OCP_CPU_12_N.4 223.31,-34.67 ; 226.66,-10.68 P_CPU_OCP_14_N.2 ; P_CPU_OCP_14_N.2 227.79,-10.68 ; P_CPU_OCP_14_N.2 226.66,-11.81 ; P_CPU_OCP_14_N.2 227.79,-11.81 ; P_CPU_OCP_11_P.2 258.73,-21.92 ; P_CPU_OCP_11_P.2 258.73,-23.05 ; P_CPU_OCP_11_P.2 257.6,-23.05 ; P_CPU_OCP_11_P.2 257.6,-21.92 ; P_CPU_OCP_11_P.5 263.03,-21.92 ; P_CPU_OCP_11_P.5 261.9,-23.05 ; P_CPU_OCP_11_P.5 263.03,-23.05 ; P_CPU_OCP_11_P.5 261.9,-21.92 ; 246.17,-34.3 P_CPU_OCP_12_N.4 ; P_CPU_OCP_12_N.4 247.3,-35.43 ; P_CPU_OCP_12_N.4 246.17,-35.43 ; P_CPU_OCP_12_N.4 247.3,-34.3 ; P_CPU_OCP_15_N.2 259.68,-8.27 ; P_CPU_OCP_15_N.2 258.55,-8.27 ; P_CPU_OCP_15_N.2 259.68,-7.14 ; P_CPU_OCP_15_N.2 258.55,-7.14 ; 204.75,-40.67 BD2_P_OCP_CPU_0_P.4 ; BD2_P_OCP_CPU_0_P.4 205.88,-40.67 ; BD2_P_OCP_CPU_0_P.4 204.75,-41.8 ; BD2_P_OCP_CPU_0_P.4 205.88,-41.8 ; 223.31,-21.16 P_OCP_CPU_12_P.2 ; P_OCP_CPU_12_P.2 224.44,-22.29 ; P_OCP_CPU_12_P.2 224.44,-21.16 ; P_OCP_CPU_12_P.2 223.31,-22.29 ; 223.31,-53.05 P_OCP_CPU_8_N.5 ; P_OCP_CPU_8_N.5 224.44,-53.05 ; P_OCP_CPU_8_N.5 223.31,-54.18 ; P_OCP_CPU_8_N.5 224.44,-54.18 ; P_OCP_CPU_13_P.2 182.07,-23.24 ; P_OCP_CPU_13_P.2 180.94,-23.24 ; P_OCP_CPU_13_P.2 182.07,-22.11 ; P_OCP_CPU_13_P.2 180.94,-22.11 ; P_OCP_CPU_9_P.5 217.31,-45.15 ; P_OCP_CPU_9_P.5 216.18,-45.15 ; P_OCP_CPU_9_P.5 216.18,-44.02 ; P_OCP_CPU_9_P.5 217.31,-44.02 ; 200.45,-44.02 BD2_P_OCP_CPU_0_P.2 ; BD2_P_OCP_CPU_0_P.2 201.58,-44.02 ; BD2_P_OCP_CPU_0_P.2 200.45,-45.15 ; BD2_P_OCP_CPU_0_P.2 201.58,-45.15 ; 204.75,-44.02 BD2_P_OCP_CPU_0_P.5 ; BD2_P_OCP_CPU_0_P.5 205.88,-44.02 ; BD2_P_OCP_CPU_0_P.5 205.88,-45.15 ; BD2_P_OCP_CPU_0_P.5 204.75,-45.15 ; 257.6,-18.57 P_CPU_OCP_11_P.3 ; P_CPU_OCP_11_P.3 258.73,-19.7 ; P_CPU_OCP_11_P.3 258.73,-18.57 ; P_CPU_OCP_11_P.3 257.6,-19.7 ; 223.31,-30.19 P_OCP_CPU_12_N.5 ; P_OCP_CPU_12_N.5 224.44,-30.19 ; P_OCP_CPU_12_N.5 224.44,-31.32 ; P_OCP_CPU_12_N.5 223.31,-31.32 ; P_CPU_OCP_8_P.3 258.73,-42.56 ; P_CPU_OCP_8_P.3 257.6,-41.43 ; P_CPU_OCP_8_P.3 257.6,-42.56 ; P_CPU_OCP_8_P.3 258.73,-41.43 ; 184.02,-52.5 P15.2 ; P15.2 184.02,-51.03 ; P15.2 185.49,-52.5 ; P15.2 185.49,-51.03 ; P_OCP_CPU_14_P.2 191.1,-7.51 ; P_OCP_CPU_14_P.2 189.97,-7.51 ; P_OCP_CPU_14_P.2 189.97,-6.38 ; P_OCP_CPU_14_P.2 191.1,-6.38 ; 258.55,-12.57 P_CPU_OCP_15_N.5 ; P_CPU_OCP_15_N.5 258.55,-11.44 ; P_CPU_OCP_15_N.5 259.68,-12.57 ; P_CPU_OCP_15_N.5 259.68,-11.44 ; P_CPU_OCP_12_P.4 251.6,-18.57 ; P_CPU_OCP_12_P.4 250.47,-18.57 ; P_CPU_OCP_12_P.4 250.47,-19.7 ; P_CPU_OCP_12_P.4 251.6,-19.7 ; 250.47,-35.43 P_CPU_OCP_12_N.3 ; P_CPU_OCP_12_N.3 251.6,-35.43 ; P_CPU_OCP_12_N.3 251.6,-34.3 ; P_CPU_OCP_12_N.3 250.47,-34.3 ; P_BD2_CLK1_N.5 213.96,-73.16 ; P_BD2_CLK1_N.5 213.96,-74.29 ; P_BD2_CLK1_N.5 212.83,-74.29 ; P_BD2_CLK1_N.5 212.83,-73.16 ; P_OCP_CPU_14_N.5 182.07,-7.51 ; P_OCP_CPU_14_N.5 180.94,-6.38 ; P_OCP_CPU_14_N.5 180.94,-7.51 ; P_OCP_CPU_14_N.5 182.07,-6.38 ; 204.75,-22.29 P_OCP_CPU_10_P.5 ; P_OCP_CPU_10_P.5 204.75,-21.16 ; P_OCP_CPU_10_P.5 205.88,-21.16 ; P_OCP_CPU_10_P.5 205.88,-22.29 ; P_OCP_CPU_9_P.2 213.01,-45.15 ; P_OCP_CPU_9_P.2 213.01,-44.02 ; P_OCP_CPU_9_P.2 211.88,-45.15 ; P_OCP_CPU_9_P.2 211.88,-44.02 ; P_BD2_CLK1_P.5 204.93,-69.99 ; P_BD2_CLK1_P.5 204.93,-68.86 ; P_BD2_CLK1_P.5 203.8,-69.99 ; P_BD2_CLK1_P.5 203.8,-68.86 ; BD2_P_OCP_CPU_0_N.4 201.58,-56.4 ; BD2_P_OCP_CPU_0_N.4 200.45,-57.53 ; BD2_P_OCP_CPU_0_N.4 200.45,-56.4 ; BD2_P_OCP_CPU_0_N.4 201.58,-57.53 ; P_OCP_CPU_8_N.4 224.44,-57.53 ; P_OCP_CPU_8_N.4 224.44,-56.4 ; P_OCP_CPU_8_N.4 223.31,-56.4 ; P_OCP_CPU_8_N.4 223.31,-57.53 ; P_OCP_CPU_12_N.3 228.74,-33.54 ; P_OCP_CPU_12_N.3 228.74,-34.67 ; P_OCP_CPU_12_N.3 227.61,-34.67 ; P_OCP_CPU_12_N.3 227.61,-33.54 ; P_OCP_CPU_10_N.4 201.58,-34.67 ; P_OCP_CPU_10_N.4 201.58,-33.54 ; P_OCP_CPU_10_N.4 200.45,-34.67 ; P_OCP_CPU_10_N.4 200.45,-33.54 ; P_OCP_CPU_11_N.2 217.31,-30.19 ; P_OCP_CPU_11_N.2 216.18,-31.32 ; P_OCP_CPU_11_N.2 216.18,-30.19 ; P_OCP_CPU_11_N.2 217.31,-31.32 ; 261.9,-12.57 P_CPU_OCP_15_N.4 ; P_CPU_OCP_15_N.4 261.9,-11.44 ; P_CPU_OCP_15_N.4 263.03,-11.44 ; P_CPU_OCP_15_N.4 263.03,-12.57 ; 211.88,-40.67 P_OCP_CPU_9_P.3 ; P_OCP_CPU_9_P.3 213.01,-40.67 ; P_OCP_CPU_9_P.3 211.88,-41.8 ; P_OCP_CPU_9_P.3 213.01,-41.8 ; 216.18,-74.29 P_BD2_CLK1_N.4 ; P_BD2_CLK1_N.4 217.31,-73.16 ; P_BD2_CLK1_N.4 216.18,-73.16 ; P_BD2_CLK1_N.4 217.31,-74.29 ; 258.55,-68.86 P_BD2_CLK2_N.2 ; P_BD2_CLK2_N.2 259.68,-68.86 ; P_BD2_CLK2_N.2 259.68,-69.99 ; P_BD2_CLK2_N.2 258.55,-69.99 ; P_BD2_CLK0_P.2 227.79,-74.29 ; P_BD2_CLK0_P.2 226.66,-74.29 ; P_BD2_CLK0_P.2 226.66,-73.16 ; P_BD2_CLK0_P.2 227.79,-73.16 ; 203.8,-7.51 P_OCP_CPU_15_N.5 ; P_OCP_CPU_15_N.5 204.93,-7.51 ; P_OCP_CPU_15_N.5 203.8,-6.38 ; P_OCP_CPU_15_N.5 204.93,-6.38 ; 211.88,-17.81 P_OCP_CPU_11_P.3 ; P_OCP_CPU_11_P.3 211.88,-18.94 ; P_OCP_CPU_11_P.3 213.01,-18.94 ; P_OCP_CPU_11_P.3 213.01,-17.81 ; 211.88,-56.4 P_OCP_CPU_9_N.4 ; P_OCP_CPU_9_N.4 213.01,-57.53 ; P_OCP_CPU_9_N.4 211.88,-57.53 ; P_OCP_CPU_9_N.4 213.01,-56.4 ; P_BD2_CLK1_N.2 213.96,-69.99 ; P_BD2_CLK1_N.2 212.83,-68.86 ; P_BD2_CLK1_N.2 213.96,-68.86 ; P_BD2_CLK1_N.2 212.83,-69.99 ; P_OCP_CPU_10_P.2 201.58,-21.16 ; P_OCP_CPU_10_P.2 201.58,-22.29 ; P_OCP_CPU_10_P.2 200.45,-21.16 ; P_OCP_CPU_10_P.2 200.45,-22.29 ; 227.61,-17.81 P_OCP_CPU_12_P.4 ; P_OCP_CPU_12_P.4 227.61,-18.94 ; P_OCP_CPU_12_P.4 228.74,-17.81 ; P_OCP_CPU_12_P.4 228.74,-18.94 ; P_OCP_CPU_13_P.4 178.72,-17.81 ; P_OCP_CPU_13_P.4 178.72,-18.94 ; P_OCP_CPU_13_P.4 177.59,-17.81 ; P_OCP_CPU_13_P.4 177.59,-18.94 ; P_BD2_CLK1_N.3 217.31,-68.86 ; P_BD2_CLK1_N.3 217.31,-69.99 ; P_BD2_CLK1_N.3 216.18,-68.86 ; P_BD2_CLK1_N.3 216.18,-69.99 ; P_BD2_CLK1_P.4 201.58,-68.86 ; P_BD2_CLK1_P.4 201.58,-69.99 ; P_BD2_CLK1_P.4 200.45,-69.99 ; P_BD2_CLK1_P.4 200.45,-68.86 ; P_CPU_OCP_9_P.5 251.6,-44.78 ; P_CPU_OCP_9_P.5 250.47,-45.91 ; P_CPU_OCP_9_P.5 251.6,-45.91 ; P_CPU_OCP_9_P.5 250.47,-44.78 ; P_OCP_CPU_15_P.2 213.96,-6.38 ; P_OCP_CPU_15_P.2 212.83,-7.51 ; P_OCP_CPU_15_P.2 212.83,-6.38 ; P_OCP_CPU_15_P.2 213.96,-7.51 ; P_CPU_OCP_13_N.2 240.17,-31.32 ; P_CPU_OCP_13_N.2 239.04,-31.32 ; P_CPU_OCP_13_N.2 240.17,-30.19 ; P_CPU_OCP_13_N.2 239.04,-30.19 ; 227.61,-30.19 P_OCP_CPU_12_N.2 ; P_OCP_CPU_12_N.2 228.74,-30.19 ; P_OCP_CPU_12_N.2 228.74,-31.32 ; P_OCP_CPU_12_N.2 227.61,-31.32 ; P_OCP_CPU_15_P.4 217.31,-10.68 ; P_OCP_CPU_15_P.4 216.18,-10.68 ; P_OCP_CPU_15_P.4 217.31,-11.81 ; P_OCP_CPU_15_P.4 216.18,-11.81 ; P_CPU_OCP_12_N.5 247.3,-30.95 ; P_CPU_OCP_12_N.5 246.17,-30.95 ; P_CPU_OCP_12_N.5 247.3,-32.08 ; P_CPU_OCP_12_N.5 246.17,-32.08 ; 176.32,-69.81 P_BD2_TRIG_IN_N.5 ; P_BD2_TRIG_IN_N.5 176.32,-70.94 ; P_BD2_TRIG_IN_N.5 177.45,-69.81 ; P_BD2_TRIG_IN_N.5 177.45,-70.94 ; 250.47,-53.81 P_CPU_OCP_9_N.2 ; P_CPU_OCP_9_N.2 251.6,-54.94 ; P_CPU_OCP_9_N.2 250.47,-54.94 ; P_CPU_OCP_9_N.2 251.6,-53.81 ; P_OCP_CPU_10_P.4 205.88,-17.81 ; P_OCP_CPU_10_P.4 205.88,-18.94 ; P_OCP_CPU_10_P.4 204.75,-18.94 ; P_OCP_CPU_10_P.4 204.75,-17.81 ; P_OCP_CPU_11_P.2 213.01,-22.29 ; P_OCP_CPU_11_P.2 211.88,-22.29 ; P_OCP_CPU_11_P.2 211.88,-21.16 ; P_OCP_CPU_11_P.2 213.01,-21.16 ; P_CPU_OCP_14_P.2 236.82,-7.51 ; P_CPU_OCP_14_P.2 235.69,-6.38 ; P_CPU_OCP_14_P.2 235.69,-7.51 ; P_CPU_OCP_14_P.2 236.82,-6.38 ; P_CPU_OCP_10_P.2 235.87,-45.15 ; P_CPU_OCP_10_P.2 235.87,-44.02 ; P_CPU_OCP_10_P.2 234.74,-45.15 ; P_CPU_OCP_10_P.2 234.74,-44.02 ; 211.88,-31.32 P_OCP_CPU_11_N.5 ; P_OCP_CPU_11_N.5 213.01,-31.32 ; P_OCP_CPU_11_N.5 213.01,-30.19 ; P_OCP_CPU_11_N.5 211.88,-30.19 ; P_CPU_OCP_14_N.3 224.44,-10.68 ; P_CPU_OCP_14_N.3 223.31,-11.81 ; P_CPU_OCP_14_N.3 223.31,-10.68 ; P_CPU_OCP_14_N.3 224.44,-11.81 ; 226.66,-6.38 P_CPU_OCP_14_N.5 ; P_CPU_OCP_14_N.5 227.79,-7.51 ; P_CPU_OCP_14_N.5 227.79,-6.38 ; P_CPU_OCP_14_N.5 226.66,-7.51 ; 216.18,-40.67 P_OCP_CPU_9_P.4 ; P_OCP_CPU_9_P.4 216.18,-41.8 ; P_OCP_CPU_9_P.4 217.31,-40.67 ; P_OCP_CPU_9_P.4 217.31,-41.8 ; P_CPU_OCP_13_P.3 235.87,-18.94 ; P_CPU_OCP_13_P.3 234.74,-18.94 ; P_CPU_OCP_13_P.3 234.74,-17.81 ; P_CPU_OCP_13_P.3 235.87,-17.81 ; P_OCP_CPU_14_N.3 178.72,-11.81 ; P_OCP_CPU_14_N.3 177.59,-11.81 ; P_OCP_CPU_14_N.3 177.59,-10.68 ; P_OCP_CPU_14_N.3 178.72,-10.68 ; P_OCP_CPU_14_P.5 191.1,-10.68 ; P_OCP_CPU_14_P.5 189.97,-10.68 ; P_OCP_CPU_14_P.5 189.97,-11.81 ; P_OCP_CPU_14_P.5 191.1,-11.81 ; P_CPU_OCP_11_N.4 258.73,-35.43 ; P_CPU_OCP_11_N.4 257.6,-35.43 ; P_CPU_OCP_11_N.4 257.6,-34.3 ; P_CPU_OCP_11_N.4 258.73,-34.3 ; 200.45,-7.51 P_OCP_CPU_15_N.4 ; P_OCP_CPU_15_N.4 201.58,-6.38 ; P_OCP_CPU_15_N.4 201.58,-7.51 ; P_OCP_CPU_15_N.4 200.45,-6.38 ; 223.31,-44.02 P_OCP_CPU_8_P.2 ; P_OCP_CPU_8_P.2 224.44,-44.02 ; P_OCP_CPU_8_P.2 223.31,-45.15 ; P_OCP_CPU_8_P.2 224.44,-45.15 ; 180.62,-58.56 P_BD2_TRIG_IN_P.4 ; P_BD2_TRIG_IN_P.4 181.75,-58.56 ; P_BD2_TRIG_IN_P.4 180.62,-57.43 ; P_BD2_TRIG_IN_P.4 181.75,-57.43 ; P_OCP_CPU_10_P.3 201.58,-18.94 ; P_OCP_CPU_10_P.3 200.45,-18.94 ; P_OCP_CPU_10_P.3 200.45,-17.81 ; P_OCP_CPU_10_P.3 201.58,-17.81 ; 227.61,-57.53 P_OCP_CPU_8_N.3 ; P_OCP_CPU_8_N.3 227.61,-56.4 ; P_OCP_CPU_8_N.3 228.74,-56.4 ; P_OCP_CPU_8_N.3 228.74,-57.53 ; P_CPU_OCP_12_P.5 251.6,-23.05 ; P_CPU_OCP_12_P.5 250.47,-23.05 ; P_CPU_OCP_12_P.5 251.6,-21.92 ; P_CPU_OCP_12_P.5 250.47,-21.92 ; P_BD2_TRIG_IN_N.2 181.75,-70.94 ; P_BD2_TRIG_IN_N.2 180.62,-70.94 ; P_BD2_TRIG_IN_N.2 180.62,-69.81 ; P_BD2_TRIG_IN_N.2 181.75,-69.81 ; P_OCP_CPU_8_N.2 228.74,-54.18 ; P_OCP_CPU_8_N.2 228.74,-53.05 ; P_OCP_CPU_8_N.2 227.61,-54.18 ; P_OCP_CPU_8_N.2 227.61,-53.05 ; P_CPU_OCP_10_N.2 240.17,-53.05 ; P_CPU_OCP_10_N.2 239.04,-54.18 ; P_CPU_OCP_10_N.2 240.17,-54.18 ; P_CPU_OCP_10_N.2 239.04,-53.05 ; 204.75,-33.54 P_OCP_CPU_10_N.3 ; P_OCP_CPU_10_N.3 205.88,-33.54 ; P_OCP_CPU_10_N.3 205.88,-34.67 ; P_OCP_CPU_10_N.3 204.75,-34.67 ; 176.32,-60.78 P_BD2_TRIG_IN_P.2 ; P_BD2_TRIG_IN_P.2 177.45,-60.78 ; P_BD2_TRIG_IN_P.2 177.45,-61.91 ; P_BD2_TRIG_IN_P.2 176.32,-61.91 ; 227.61,-22.29 P_OCP_CPU_12_P.5 ; P_OCP_CPU_12_P.5 228.74,-22.29 ; P_OCP_CPU_12_P.5 228.74,-21.16 ; P_OCP_CPU_12_P.5 227.61,-21.16 ; P_OCP_CPU_9_N.3 217.31,-56.4 ; P_OCP_CPU_9_N.3 216.18,-57.53 ; P_OCP_CPU_9_N.3 216.18,-56.4 ; P_OCP_CPU_9_N.3 217.31,-57.53 ; 261.9,-68.86 P_BD2_CLK2_N.3 ; P_BD2_CLK2_N.3 263.03,-69.99 ; P_BD2_CLK2_N.3 263.03,-68.86 ; P_BD2_CLK2_N.3 261.9,-69.99 ; 257.6,-45.91 P_CPU_OCP_8_P.2 ; P_CPU_OCP_8_P.2 258.73,-44.78 ; P_CPU_OCP_8_P.2 258.73,-45.91 ; P_CPU_OCP_8_P.2 257.6,-44.78 ; 226.66,-68.86 P_BD2_CLK0_P.5 ; P_BD2_CLK0_P.5 227.79,-69.99 ; P_BD2_CLK0_P.5 227.79,-68.86 ; P_BD2_CLK0_P.5 226.66,-69.99 ; 227.61,-45.15 P_OCP_CPU_8_P.5 ; P_OCP_CPU_8_P.5 228.74,-44.02 ; P_OCP_CPU_8_P.5 227.61,-44.02 ; P_OCP_CPU_8_P.5 228.74,-45.15 ; 258.55,-74.29 P_BD2_CLK2_N.5 ; P_BD2_CLK2_N.5 259.68,-74.29 ; P_BD2_CLK2_N.5 258.55,-73.16 ; P_BD2_CLK2_N.5 259.68,-73.16 ; P_CPU_OCP_10_P.5 240.17,-45.15 ; P_CPU_OCP_10_P.5 240.17,-44.02 ; P_CPU_OCP_10_P.5 239.04,-44.02 ; P_CPU_OCP_10_P.5 239.04,-45.15 ; P_OCP_CPU_11_N.3 217.31,-34.67 ; P_OCP_CPU_11_N.3 216.18,-33.54 ; P_OCP_CPU_11_N.3 217.31,-33.54 ; P_OCP_CPU_11_N.3 216.18,-34.67 ; P_BD2_CLK0_P.4 224.44,-68.86 ; P_BD2_CLK0_P.4 223.31,-69.99 ; P_BD2_CLK0_P.4 224.44,-69.99 ; P_BD2_CLK0_P.4 223.31,-68.86 ; P_CPU_OCP_10_P.4 240.17,-40.67 ; P_CPU_OCP_10_P.4 239.04,-41.8 ; P_CPU_OCP_10_P.4 240.17,-41.8 ; P_CPU_OCP_10_P.4 239.04,-40.67 ; 249.52,-12.57 P_CPU_OCP_15_P.2 ; P_CPU_OCP_15_P.2 250.65,-12.57 ; P_CPU_OCP_15_P.2 249.52,-11.44 ; P_CPU_OCP_15_P.2 250.65,-11.44 ; P_OCP_CPU_13_N.3 194.45,-17.81 ; P_OCP_CPU_13_N.3 193.32,-17.81 ; P_OCP_CPU_13_N.3 194.45,-18.94 ; P_OCP_CPU_13_N.3 193.32,-18.94 ; P_OCP_CPU_8_P.4 228.74,-40.67 ; P_OCP_CPU_8_P.4 228.74,-41.8 ; P_OCP_CPU_8_P.4 227.61,-41.8 ; P_OCP_CPU_8_P.4 227.61,-40.67 ; P_CPU_OCP_11_N.3 263.03,-35.43 ; P_CPU_OCP_11_N.3 261.9,-34.3 ; P_CPU_OCP_11_N.3 261.9,-35.43 ; P_CPU_OCP_11_N.3 263.03,-34.3 ; BD2_P_OCP_CPU_0_N.5 201.58,-54.18 ; BD2_P_OCP_CPU_0_N.5 200.45,-54.18 ; BD2_P_OCP_CPU_0_N.5 201.58,-53.05 ; BD2_P_OCP_CPU_0_N.5 200.45,-53.05 ; BD2_P_OCP_CPU_0_N.2 205.88,-53.05 ; BD2_P_OCP_CPU_0_N.2 204.75,-53.05 ; BD2_P_OCP_CPU_0_N.2 205.88,-54.18 ; BD2_P_OCP_CPU_0_N.2 204.75,-54.18 ; 180.94,-10.68 P_OCP_CPU_14_N.2 ; P_OCP_CPU_14_N.2 182.07,-10.68 ; P_OCP_CPU_14_N.2 180.94,-11.81 ; P_OCP_CPU_14_N.2 182.07,-11.81 ; P_CPU_OCP_8_N.3 263.03,-58.29 ; P_CPU_OCP_8_N.3 261.9,-58.29 ; P_CPU_OCP_8_N.3 263.03,-57.16 ; P_CPU_OCP_8_N.3 261.9,-57.16 ; P_CPU_OCP_14_P.5 236.82,-11.81 ; P_CPU_OCP_14_P.5 235.69,-10.68 ; P_CPU_OCP_14_P.5 235.69,-11.81 ; P_CPU_OCP_14_P.5 236.82,-10.68 ; P_CPU_OCP_10_N.4 235.87,-57.53 ; P_CPU_OCP_10_N.4 234.74,-56.4 ; P_CPU_OCP_10_N.4 235.87,-56.4 ; P_CPU_OCP_10_N.4 234.74,-57.53 ; P_CPU_OCP_11_N.2 263.03,-30.95 ; P_CPU_OCP_11_N.2 261.9,-32.08 ; P_CPU_OCP_11_N.2 261.9,-30.95 ; P_CPU_OCP_11_N.2 263.03,-32.08 ; P_OCP_CPU_9_N.5 213.01,-53.05 ; P_OCP_CPU_9_N.5 211.88,-54.18 ; P_OCP_CPU_9_N.5 213.01,-54.18 ; P_OCP_CPU_9_N.5 211.88,-53.05 ; P_BD2_CLK2_P.5 250.65,-68.86 ; P_BD2_CLK2_P.5 249.52,-68.86 ; P_BD2_CLK2_P.5 249.52,-69.99 ; P_BD2_CLK2_P.5 250.65,-69.99 ; 235.69,-68.86 P_BD2_CLK0_N.2 ; P_BD2_CLK0_N.2 236.82,-69.99 ; P_BD2_CLK0_N.2 236.82,-68.86 ; P_BD2_CLK0_N.2 235.69,-69.99 ; 193.32,-69.81 P_BD2_CMTS_P.2 ; P_BD2_CMTS_P.2 194.45,-69.81 ; P_BD2_CMTS_P.2 194.45,-70.94 ; P_BD2_CMTS_P.2 193.32,-70.94 ; P_OCP_CPU_8_P.3 224.44,-41.8 ; P_OCP_CPU_8_P.3 223.31,-40.67 ; P_OCP_CPU_8_P.3 223.31,-41.8 ; P_OCP_CPU_8_P.3 224.44,-40.67 ; P_CPU_OCP_8_N.2 263.03,-54.94 ; P_CPU_OCP_8_N.2 261.9,-54.94 ; P_CPU_OCP_8_N.2 263.03,-53.81 ; P_CPU_OCP_8_N.2 261.9,-53.81 ; P_CPU_OCP_12_P.2 247.3,-21.92 ; P_CPU_OCP_12_P.2 246.17,-21.92 ; P_CPU_OCP_12_P.2 246.17,-23.05 ; P_CPU_OCP_12_P.2 247.3,-23.05 ; 250.47,-42.56 P_CPU_OCP_9_P.4 ; P_CPU_OCP_9_P.4 251.6,-41.43 ; P_CPU_OCP_9_P.4 251.6,-42.56 ; P_CPU_OCP_9_P.4 250.47,-41.43 ; P_BD2_TRIG_IN_P.5 181.75,-60.78 ; P_BD2_TRIG_IN_P.5 181.75,-61.91 ; P_BD2_TRIG_IN_P.5 180.62,-61.91 ; P_BD2_TRIG_IN_P.5 180.62,-60.78 ; 239.04,-57.53 P_CPU_OCP_10_N.3 ; P_CPU_OCP_10_N.3 240.17,-56.4 ; P_CPU_OCP_10_N.3 239.04,-56.4 ; P_CPU_OCP_10_N.3 240.17,-57.53 ; P_CPU_OCP_9_N.4 247.3,-57.16 ; P_CPU_OCP_9_N.4 247.3,-58.29 ; P_CPU_OCP_9_N.4 246.17,-57.16 ; P_CPU_OCP_9_N.4 246.17,-58.29 ; P_BD2_CLK1_P.2 204.93,-74.29 ; P_BD2_CLK1_P.2 204.93,-73.16 ; P_BD2_CLK1_P.2 203.8,-73.16 ; P_BD2_CLK1_P.2 203.8,-74.29 ; P_OCP_CPU_10_N.5 201.58,-30.19 ; P_OCP_CPU_10_N.5 201.58,-31.32 ; P_OCP_CPU_10_N.5 200.45,-30.19 ; P_OCP_CPU_10_N.5 200.45,-31.32 ; P_CPU_OCP_9_N.3 251.6,-57.16 ; P_CPU_OCP_9_N.3 250.47,-58.29 ; P_CPU_OCP_9_N.3 250.47,-57.16 ; P_CPU_OCP_9_N.3 251.6,-58.29 ; P_OCP_CPU_12_P.3 224.44,-17.81 ; P_OCP_CPU_12_P.3 223.31,-17.81 ; P_OCP_CPU_12_P.3 223.31,-18.94 ; P_OCP_CPU_12_P.3 224.44,-18.94 ; 239.04,-18.94 P_CPU_OCP_13_P.4 ; P_CPU_OCP_13_P.4 240.17,-17.81 ; P_CPU_OCP_13_P.4 240.17,-18.94 ; P_CPU_OCP_13_P.4 239.04,-17.81 ; 204.75,-30.19 P_OCP_CPU_10_N.2 ; P_OCP_CPU_10_N.2 205.88,-31.32 ; P_OCP_CPU_10_N.2 205.88,-30.19 ; P_OCP_CPU_10_N.2 204.75,-31.32 ; P_CPU_OCP_8_N.5 258.73,-54.94 ; P_CPU_OCP_8_N.5 257.6,-54.94 ; P_CPU_OCP_8_N.5 258.73,-53.81 ; P_CPU_OCP_8_N.5 257.6,-53.81 ; P_OCP_CPU_13_N.4 194.45,-22.11 ; P_OCP_CPU_13_N.4 193.32,-23.24 ; P_OCP_CPU_13_N.4 194.45,-23.24 ; P_OCP_CPU_13_N.4 193.32,-22.11 ; 180.62,-74.29 P_BD2_TRIG_IN_N.3 ; P_BD2_TRIG_IN_N.3 181.75,-73.16 ; P_BD2_TRIG_IN_N.3 180.62,-73.16 ; P_BD2_TRIG_IN_N.3 181.75,-74.29 ; P_OCP_CPU_14_P.4 194.45,-11.81 ; P_OCP_CPU_14_P.4 193.32,-10.68 ; P_OCP_CPU_14_P.4 193.32,-11.81 ; P_OCP_CPU_14_P.4 194.45,-10.68 ; 261.9,-7.14 P_CPU_OCP_15_N.3 ; P_CPU_OCP_15_N.3 261.9,-8.27 ; P_CPU_OCP_15_N.3 263.03,-8.27 ; P_CPU_OCP_15_N.3 263.03,-7.14 ; P_BD2_CLK2_P.2 250.65,-73.16 ; P_BD2_CLK2_P.2 250.65,-74.29 ; P_BD2_CLK2_P.2 249.52,-74.29 ; P_BD2_CLK2_P.2 249.52,-73.16 ; 189.02,-58.56 P_BD2_CMTS_N.3 ; P_BD2_CMTS_N.3 190.15,-57.43 ; P_BD2_CMTS_N.3 190.15,-58.56 ; P_BD2_CMTS_N.3 189.02,-57.43 ; P_OCP_CPU_15_P.3 217.31,-6.38 ; P_OCP_CPU_15_P.3 217.31,-7.51 ; P_OCP_CPU_15_P.3 216.18,-7.51 ; P_OCP_CPU_15_P.3 216.18,-6.38 ; P_CPU_OCP_8_P.5 263.03,-45.91 ; P_CPU_OCP_8_P.5 263.03,-44.78 ; P_CPU_OCP_8_P.5 261.9,-44.78 ; P_CPU_OCP_8_P.5 261.9,-45.91 ; 239.04,-22.29 P_CPU_OCP_13_P.5 ; P_CPU_OCP_13_P.5 240.17,-21.16 ; P_CPU_OCP_13_P.5 239.04,-21.16 ; P_CPU_OCP_13_P.5 240.17,-22.29 ; 234.74,-40.67 P_CPU_OCP_10_P.3 ; P_CPU_OCP_10_P.3 234.74,-41.8 ; P_CPU_OCP_10_P.3 235.87,-41.8 ; P_CPU_OCP_10_P.3 235.87,-40.67 ; 180.94,-18.94 P_OCP_CPU_13_P.5 ; P_OCP_CPU_13_P.5 182.07,-17.81 ; P_OCP_CPU_13_P.5 182.07,-18.94 ; P_OCP_CPU_13_P.5 180.94,-17.81 ; P_CPU_OCP_15_P.4 247.3,-7.14 ; P_CPU_OCP_15_P.4 246.17,-7.14 ; P_CPU_OCP_15_P.4 247.3,-8.27 ; P_CPU_OCP_15_P.4 246.17,-8.27 ; 234.74,-54.18 P_CPU_OCP_10_N.5 ; P_CPU_OCP_10_N.5 234.74,-53.05 ; P_CPU_OCP_10_N.5 235.87,-54.18 ; P_CPU_OCP_10_N.5 235.87,-53.05 ; 234.74,-33.54 P_CPU_OCP_13_N.4 ; P_CPU_OCP_13_N.4 234.74,-34.67 ; P_CPU_OCP_13_N.4 235.87,-34.67 ; P_CPU_OCP_13_N.4 235.87,-33.54 ; P_OCP_CPU_9_N.2 217.31,-53.05 ; P_OCP_CPU_9_N.2 216.18,-53.05 ; P_OCP_CPU_9_N.2 216.18,-54.18 ; P_OCP_CPU_9_N.2 217.31,-54.18 ; 193.32,-6.38 P_OCP_CPU_14_P.3 ; P_OCP_CPU_14_P.3 193.32,-7.51 ; P_OCP_CPU_14_P.3 194.45,-6.38 ; P_OCP_CPU_14_P.3 194.45,-7.51 ; 246.17,-68.86 P_BD2_CLK2_P.4 ; P_BD2_CLK2_P.4 247.3,-68.86 ; P_BD2_CLK2_P.4 246.17,-69.99 ; P_BD2_CLK2_P.4 247.3,-69.99 ; 200.45,-73.16 P_BD2_CLK1_P.3 ; P_BD2_CLK1_P.3 201.58,-73.16 ; P_BD2_CLK1_P.3 200.45,-74.29 ; P_BD2_CLK1_P.3 201.58,-74.29 ; P_OCP_CPU_15_N.3 201.58,-11.81 ; P_OCP_CPU_15_N.3 200.45,-10.68 ; P_OCP_CPU_15_N.3 201.58,-10.68 ; P_OCP_CPU_15_N.3 200.45,-11.81
  BOTTOM w0.381: v1(276.14,-65.62) v1(274.7,-65.62) ; v1(276.14,-18.71) v1(274.7,-18.71) ; P_OCP2.A25 v1(274.7,-44.43) ; P_OCP2.A29 v1(274.7,-38.62) ; P_OCP2.A32 v1(274.7,-36.82) ; v1(274.7,-49.86) 276.11,-49.86 v1(276.14,-49.83) ; v1(276.14,-16.91) v1(274.7,-16.91) ; v1(276.14,-25.91) v1(274.7,-25.91) ; P_OCP2.A19 v1(274.7,-48.03) ; v1(276.14,-11.51) v1(274.7,-11.51) ; v1(276.14,-20.51) v1(274.7,-20.51) ; P_OCP2.A28 v1(274.7,-42.63) ; v1(276.14,-24.11) v1(274.7,-24.11) ; P_OCP2.A35 v1(274.7,-35.02) ; v1(276.14,-63.82) v1(274.7,-63.82) ; v1(276.14,-13.31) v1(274.7,-13.31) ; v1(276.14,-22.31) v1(274.7,-22.31) ; v1(276.14,-15.11) v1(274.7,-15.11) ; P_OCP2.A38 v1(274.7,-33.22) ; P_OCP2.A22 v1(274.7,-46.23) ; P_OCP2.A41 v1(274.7,-31.42) ; v1(274.7,-51.63) v1(276.14,-51.63)
  vias: v1(167.1,-44.53) v1(167.1,-45.31) v1(173.7,-25.35) v1(174.59,-25.35) v1(175.48,-25.35) v1(176.37,-25.35) v1(177.26,-25.35) v1(178.15,-25.35) v1(179.04,-25.35) v1(179.93,-25.35) v1(181.2,-42.62) v1(181.19,-43.41) v1(195.04,-31.67) v1(195.04,-32.46) v1(265.4,-57.86) v1(265.4,-58.75) v1(265.4,-60.53) v1(265.4,-61.42) v1(271.54,-55.95) v1(271.54,-57.1) v1(271.54,-58.24) v1(276.95,-11.51) v1(276.95,-13.31) v1(276.95,-15.11) v1(276.95,-16.91) v1(276.95,-18.71) v1(276.95,-20.51) v1(276.95,-22.31) v1(276.95,-24.11) v1(276.95,-25.91) v1(276.95,-49.83) v1(276.95,-51.63) v1(276.95,-63.82) v1(276.95,-65.62) v2(178.29,-60.15) v2(178.29,-71.58) v2(178.39,-59.77) v2(178.39,-60.52) v2(178.39,-71.2) v2(178.39,-71.95) v2(178.66,-59.5) v2(178.66,-72.23) v2(179.04,-59.4) v2(179.04,-72.33) v2(179.41,-59.5) v2(179.41,-72.23) v2(179.69,-59.77) v2(179.69,-60.52) v2(179.69,-71.2) v2(179.69,-71.95) v2(179.79,-60.15) v2(179.79,-71.58) v2(190.99,-60.15) v2(190.99,-71.58) v2(191.09,-59.77) v2(191.09,-60.52) v2(191.09,-71.2) v2(191.09,-71.95) v2(191.36,-59.5) v2(191.36,-72.23) v2(191.74,-59.4) v2(191.74,-72.33) v2(192.11,-59.5) v2(192.11,-72.23) v2(192.39,-59.77) v2(192.39,-60.52) v2(192.39,-71.2) v2(192.39,-71.95) v2(192.49,-60.15) v2(192.49,-71.58) v2(225.28,-9.09) v2(225.28,-71.58) v2(225.38,-8.72) v2(225.38,-9.47) v2(225.38,-71.2) v2(225.38,-71.95) v2(225.65,-8.44) v2(225.65,-9.74) v2(225.65,-70.93) v2(225.65,-72.23) v2(226.03,-8.34) v2(226.03,-9.84) v2(226.03,-70.83) v2(226.03,-72.33) v2(226.4,-8.44) v2(226.4,-9.74) v2(226.4,-70.93) v2(226.4,-72.23) v2(236.71,-20.52) v2(236.71,-31.95) v2(236.71,-43.38) v2(236.71,-54.81) v2(236.81,-20.15) v2(236.81,-20.9) v2(236.81,-31.58) v2(236.81,-32.33) v2(236.81,-43.01) v2(236.81,-43.76) v2(236.81,-54.44) v2(236.81,-55.19) v2(237.08,-8.44) v2(237.08,-9.74) v2(237.08,-19.87) v2(237.08,-32.6) v2(237.08,-42.73) v2(237.08,-55.46) v2(237.08,-70.93) v2(237.08,-72.23) v2(237.46,-8.34) v2(237.46,-9.84) v2(237.46,-19.77) v2(237.46,-32.7) v2(237.46,-42.63) v2(237.46,-55.56) v2(237.46,-70.83) v2(237.46,-72.33) v2(237.83,-8.44) v2(237.83,-9.74) v2(237.83,-19.87) v2(237.83,-32.6) v2(237.83,-42.73) v2(237.83,-55.46) v2(237.83,-70.93) v2(237.83,-72.23) v2(238.11,-8.72) v2(238.11,-9.47) v2(238.11,-20.15) v2(238.11,-20.9) v2(238.11,-31.58) v2(238.11,-32.33) v2(238.11,-43.01) v2(238.11,-43.76) v2(238.11,-54.44) v2(238.11,-55.19) v2(238.11,-71.2) v2(238.11,-71.95) v2(238.21,-9.09) v2(238.21,-20.52) v2(238.21,-31.95) v2(238.21,-43.38) v2(238.21,-54.81) v2(238.21,-71.58) v2(248.14,-9.86) v2(248.14,-21.29) v2(248.14,-32.72) v2(248.14,-44.15) v2(248.14,-55.58) v2(248.14,-71.58) v2(248.24,-9.48) v2(248.24,-10.23) v2(248.24,-20.91) v2(248.24,-21.66) v2(248.24,-32.34) v2(248.24,-33.09) v2(248.24,-43.77) v2(248.24,-44.52) v2(248.24,-55.2) v2(248.24,-55.95) v2(248.24,-71.2) v2(248.24,-71.95) v2(248.51,-9.21) v2(248.51,-10.5) v2(248.51,-20.64) v2(248.51,-33.36) v2(248.51,-43.5) v2(248.51,-56.22) v2(248.51,-70.93) v2(248.51,-72.23) v2(248.89,-9.11) v2(248.89,-10.6) v2(248.89,-20.54) v2(248.89,-33.46) v2(248.89,-43.4) v2(248.89,-56.32) v2(248.89,-70.83) v2(248.89,-72.33) v2(249.26,-9.21) v2(249.26,-10.5) v2(249.26,-20.64) v2(249.26,-33.36) v2(249.26,-43.5) v2(249.26,-56.22) v2(249.26,-70.93) v2(249.26,-72.23) v2(249.54,-20.91) v2(249.54,-21.66) v2(249.54,-32.34) v2(249.54,-33.09) v2(249.54,-43.77) v2(249.54,-44.52) v2(249.54,-55.2) v2(249.54,-55.95) v2(249.64,-21.29) v2(249.64,-32.72) v2(249.64,-44.15) v2(249.64,-55.58) v2(259.57,-21.29) v2(259.57,-32.72) v2(259.57,-44.15) v2(259.57,-55.58) v2(259.67,-20.91) v2(259.67,-21.66) v2(259.67,-32.34) v2(259.67,-33.09) v2(259.67,-43.77) v2(259.67,-44.52) v2(259.67,-55.2) v2(259.67,-55.95) v2(259.94,-9.21) v2(259.94,-10.5) v2(259.94,-20.64) v2(259.94,-33.36) v2(259.94,-43.5) v2(259.94,-56.22) v2(259.94,-70.93) v2(259.94,-72.23) v2(260.32,-9.11) v2(260.32,-10.6) v2(260.32,-20.54) v2(260.32,-33.46) v2(260.32,-43.4) v2(260.32,-56.32) v2(260.32,-70.83) v2(260.32,-72.33) v2(260.69,-9.21) v2(260.69,-10.5) v2(260.69,-20.64) v2(260.69,-33.36) v2(260.69,-43.5) v2(260.69,-56.22) v2(260.69,-70.93) v2(260.69,-72.23) v2(260.97,-9.48) v2(260.97,-10.23) v2(260.97,-20.91) v2(260.97,-21.66) v2(260.97,-32.34) v2(260.97,-33.09) v2(260.97,-43.77) v2(260.97,-44.52) v2(260.97,-55.2) v2(260.97,-55.95) v2(260.97,-71.2) v2(260.97,-71.95) v2(261.07,-9.86) v2(261.07,-21.29) v2(261.07,-32.72) v2(261.07,-44.15) v2(261.07,-55.58) v2(261.07,-71.58) v3(179.61,-9.09) v3(179.61,-20.52) v3(179.7,-8.74) v3(179.7,-9.44) v3(179.7,-20.17) v3(179.7,-20.87) v3(179.96,-8.49) v3(179.96,-9.7) v3(179.96,-19.92) v3(179.96,-21.13) v3(180.31,-8.39) v3(180.31,-9.79) v3(180.31,-19.82) v3(180.31,-21.22) v3(180.66,-8.49) v3(180.66,-9.7) v3(180.66,-19.92) v3(180.66,-21.13) v3(191.39,-8.49) v3(191.39,-9.7) v3(191.39,-19.92) v3(191.39,-21.13) v3(191.74,-8.39) v3(191.74,-9.79) v3(191.74,-19.82) v3(191.74,-21.22) v3(192.09,-8.49) v3(192.09,-9.7) v3(192.09,-19.92) v3(192.09,-21.13) v3(192.34,-8.74) v3(192.34,-9.44) v3(192.34,-20.17) v3(192.34,-20.87) v3(192.44,-9.09) v3(192.44,-20.52) v3(202.47,-9.09) v3(202.47,-20.52) v3(202.47,-31.95) v3(202.47,-43.38) v3(202.47,-54.81) v3(202.47,-71.58) v3(202.56,-8.74) v3(202.56,-9.44) v3(202.56,-20.17) v3(202.56,-20.87) v3(202.56,-31.6) v3(202.56,-32.3) v3(202.56,-43.03) v3(202.56,-43.73) v3(202.56,-54.46) v3(202.56,-55.16) v3(202.56,-71.23) v3(202.56,-71.93) v3(202.82,-8.49) v3(202.82,-9.7) v3(202.82,-19.92) v3(202.82,-32.56) v3(202.82,-42.78) v3(202.82,-55.42) v3(202.82,-70.97) v3(202.82,-72.18) v3(203.17,-8.39) v3(203.17,-9.79) v3(203.17,-19.82) v3(203.17,-32.65) v3(203.17,-42.68) v3(203.17,-55.51) v3(203.17,-70.88) v3(203.17,-72.28) v3(203.52,-8.49) v3(203.52,-9.7) v3(203.52,-19.92) v3(203.52,-32.56) v3(203.52,-42.78) v3(203.52,-55.42) v3(203.52,-70.97) v3(203.52,-72.18) v3(203.77,-20.17) v3(203.77,-20.87) v3(203.77,-31.6) v3(203.77,-32.3) v3(203.77,-43.03) v3(203.77,-43.73) v3(203.77,-54.46) v3(203.77,-55.16) v3(203.87,-20.52) v3(203.87,-31.95) v3(203.87,-43.38) v3(203.87,-54.81) v3(213.9,-20.52) v3(213.9,-31.95) v3(213.9,-43.38) v3(213.9,-54.81) v3(213.99,-20.17) v3(213.99,-20.87) v3(213.99,-31.6) v3(213.99,-32.3) v3(213.99,-43.03) v3(213.99,-43.73) v3(213.99,-54.46) v3(213.99,-55.16) v3(214.25,-8.49) v3(214.25,-9.7) v3(214.25,-19.92) v3(214.25,-32.56) v3(214.25,-42.78) v3(214.25,-55.42) v3(214.25,-70.97) v3(214.25,-72.18) v3(214.6,-8.39) v3(214.6,-9.79) v3(214.6,-19.82) v3(214.6,-32.65) v3(214.6,-42.68) v3(214.6,-55.51) v3(214.6,-70.88) v3(214.6,-72.28) v3(214.95,-8.49) v3(214.95,-9.7) v3(214.95,-19.92) v3(214.95,-32.56) v3(214.95,-42.78) v3(214.95,-55.42) v3(214.95,-70.97) v3(214.95,-72.18) v3(215.2,-8.74) v3(215.2,-9.44) v3(215.2,-20.17) v3(215.2,-20.87) v3(215.2,-31.6) v3(215.2,-32.3) v3(215.2,-43.03) v3(215.2,-43.73) v3(215.2,-54.46) v3(215.2,-55.16) v3(215.2,-71.23) v3(215.2,-71.93) v3(215.3,-9.09) v3(215.3,-20.52) v3(215.3,-31.95) v3(215.3,-43.38) v3(215.3,-54.81) v3(215.3,-71.58) v3(225.33,-20.52) v3(225.33,-31.95) v3(225.33,-43.38) v3(225.33,-54.81) v3(225.42,-20.17) v3(225.42,-20.87) v3(225.42,-31.6) v3(225.42,-32.3) v3(225.42,-43.03) v3(225.42,-43.73) v3(225.42,-54.46) v3(225.42,-55.16) v3(225.68,-19.92) v3(225.68,-32.56) v3(225.68,-42.78) v3(225.68,-55.42) v3(226.03,-19.82) v3(226.03,-32.65) v3(226.03,-42.68) v3(226.03,-55.51) v3(226.38,-19.92) v3(226.38,-32.56) v3(226.38,-42.78) v3(226.38,-55.42) v3(226.63,-20.17) v3(226.73,-20.52) v3(226.63,-20.87) v3(226.63,-31.6) v3(226.73,-31.95) v3(226.63,-32.3) v3(226.63,-43.03) v3(226.73,-43.38) v3(226.63,-43.73) v3(226.63,-54.46) v3(226.73,-54.81) v3(226.63,-55.16) v4(166.14,-5.68) v4(166.14,-10.04) v4(166.14,-70.68) v4(166.14,-75.04) v4(168.32,-4.78) v4(168.32,-10.95) v4(168.32,-69.78) v4(168.32,-75.95) v4(170.5,-5.68) v4(170.5,-10.04) v4(170.5,-70.68) v4(170.5,-75.04) v4(171.41,-7.86) v4(171.41,-72.86) v5(185.64,-65.86)
